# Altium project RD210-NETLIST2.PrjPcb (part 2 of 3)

## Sheet 6.SchDoc
size 609 x 444 mm
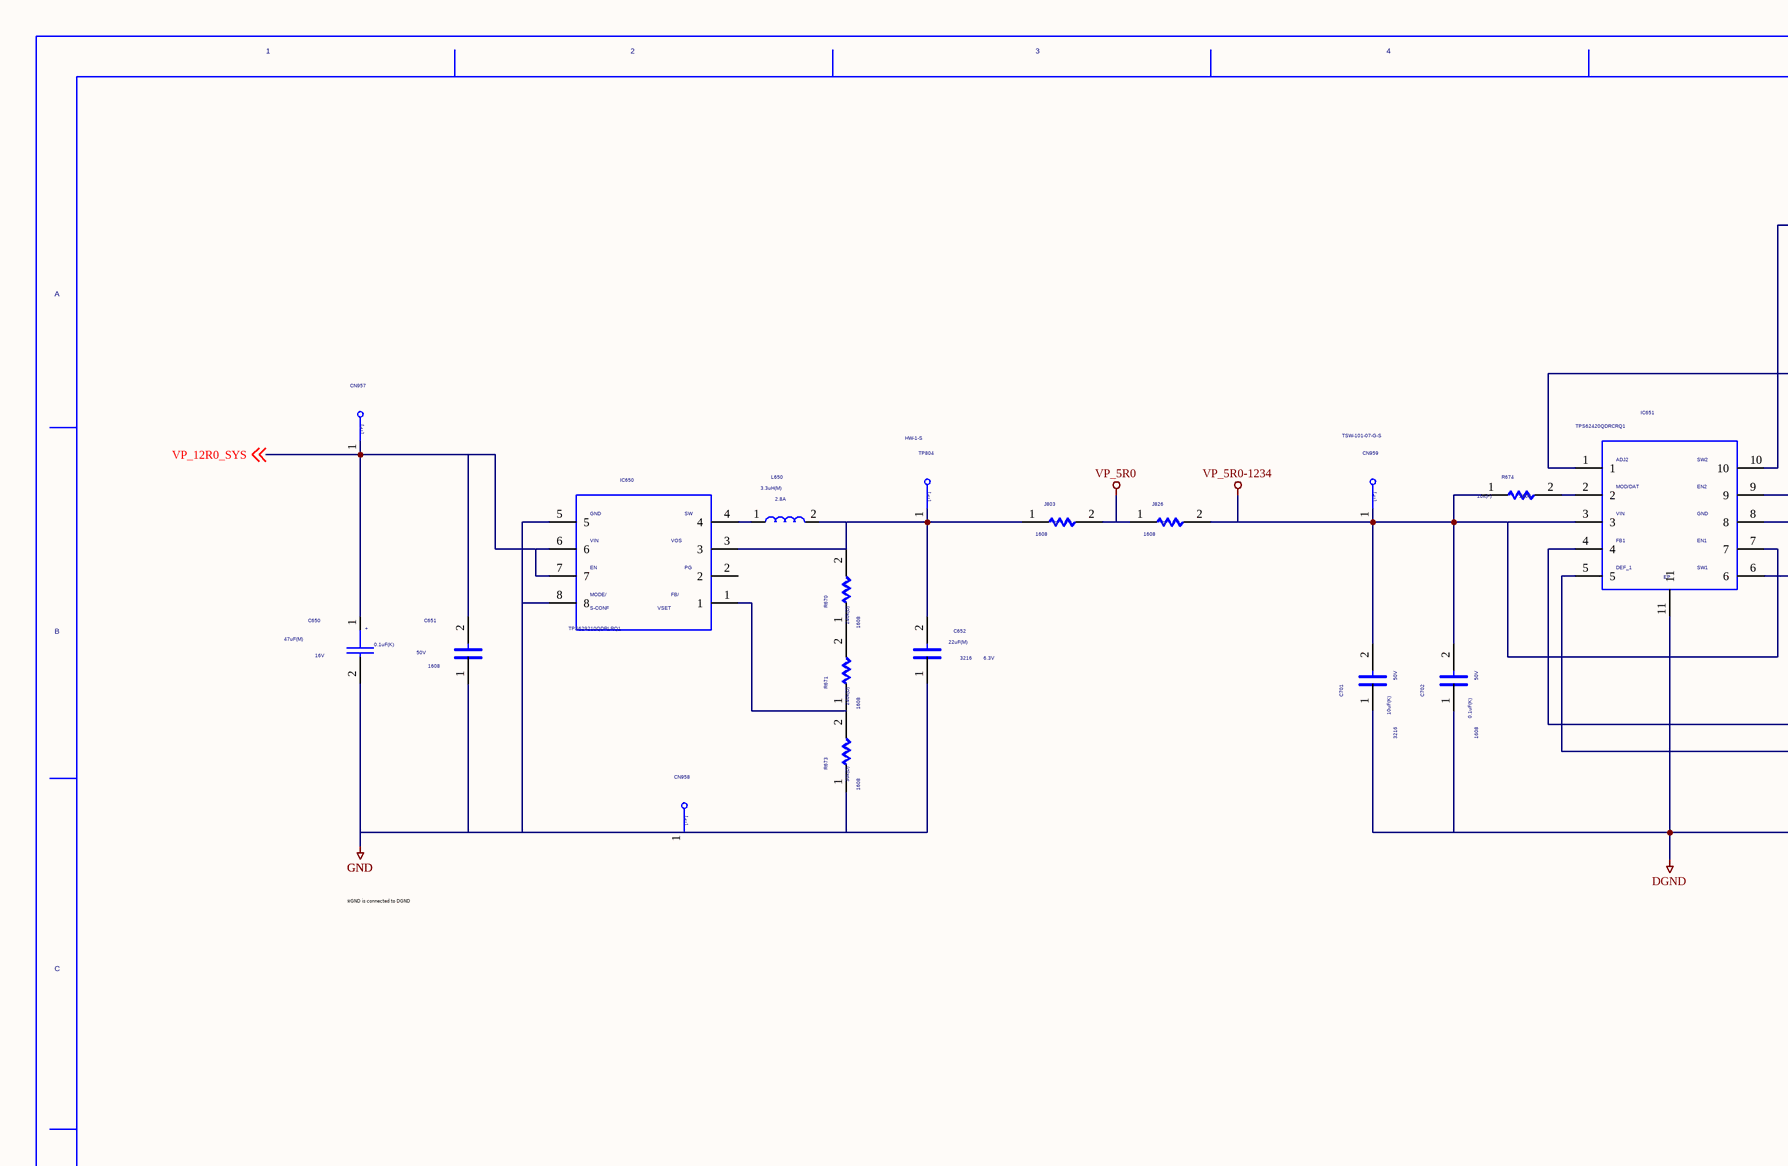
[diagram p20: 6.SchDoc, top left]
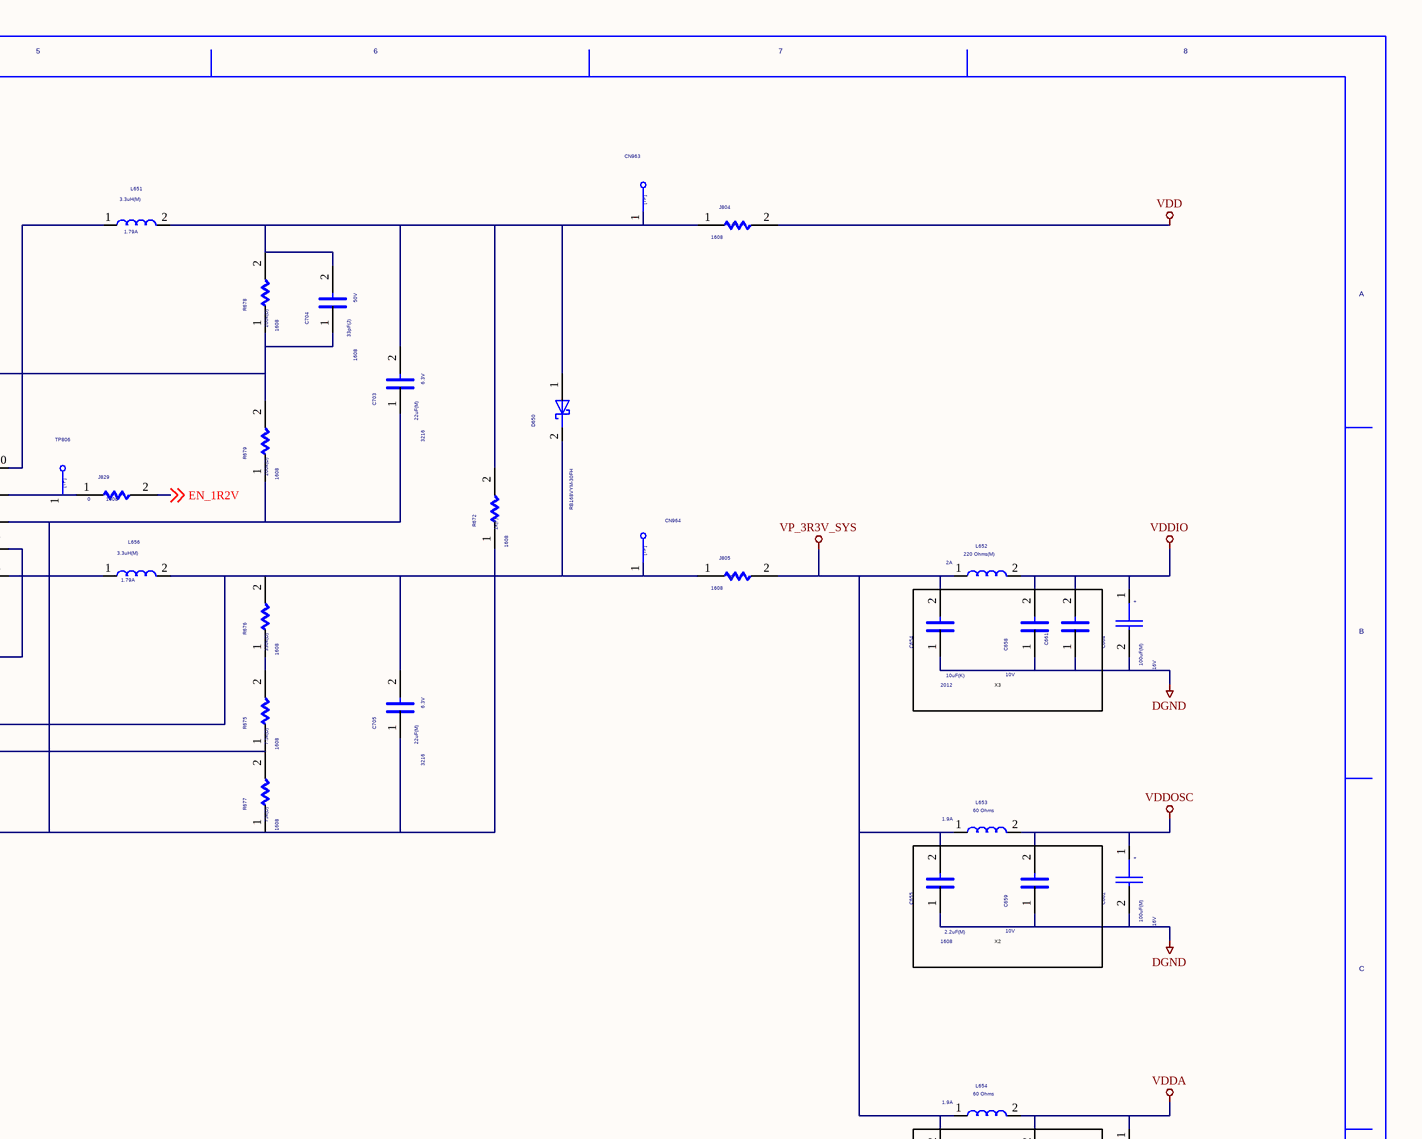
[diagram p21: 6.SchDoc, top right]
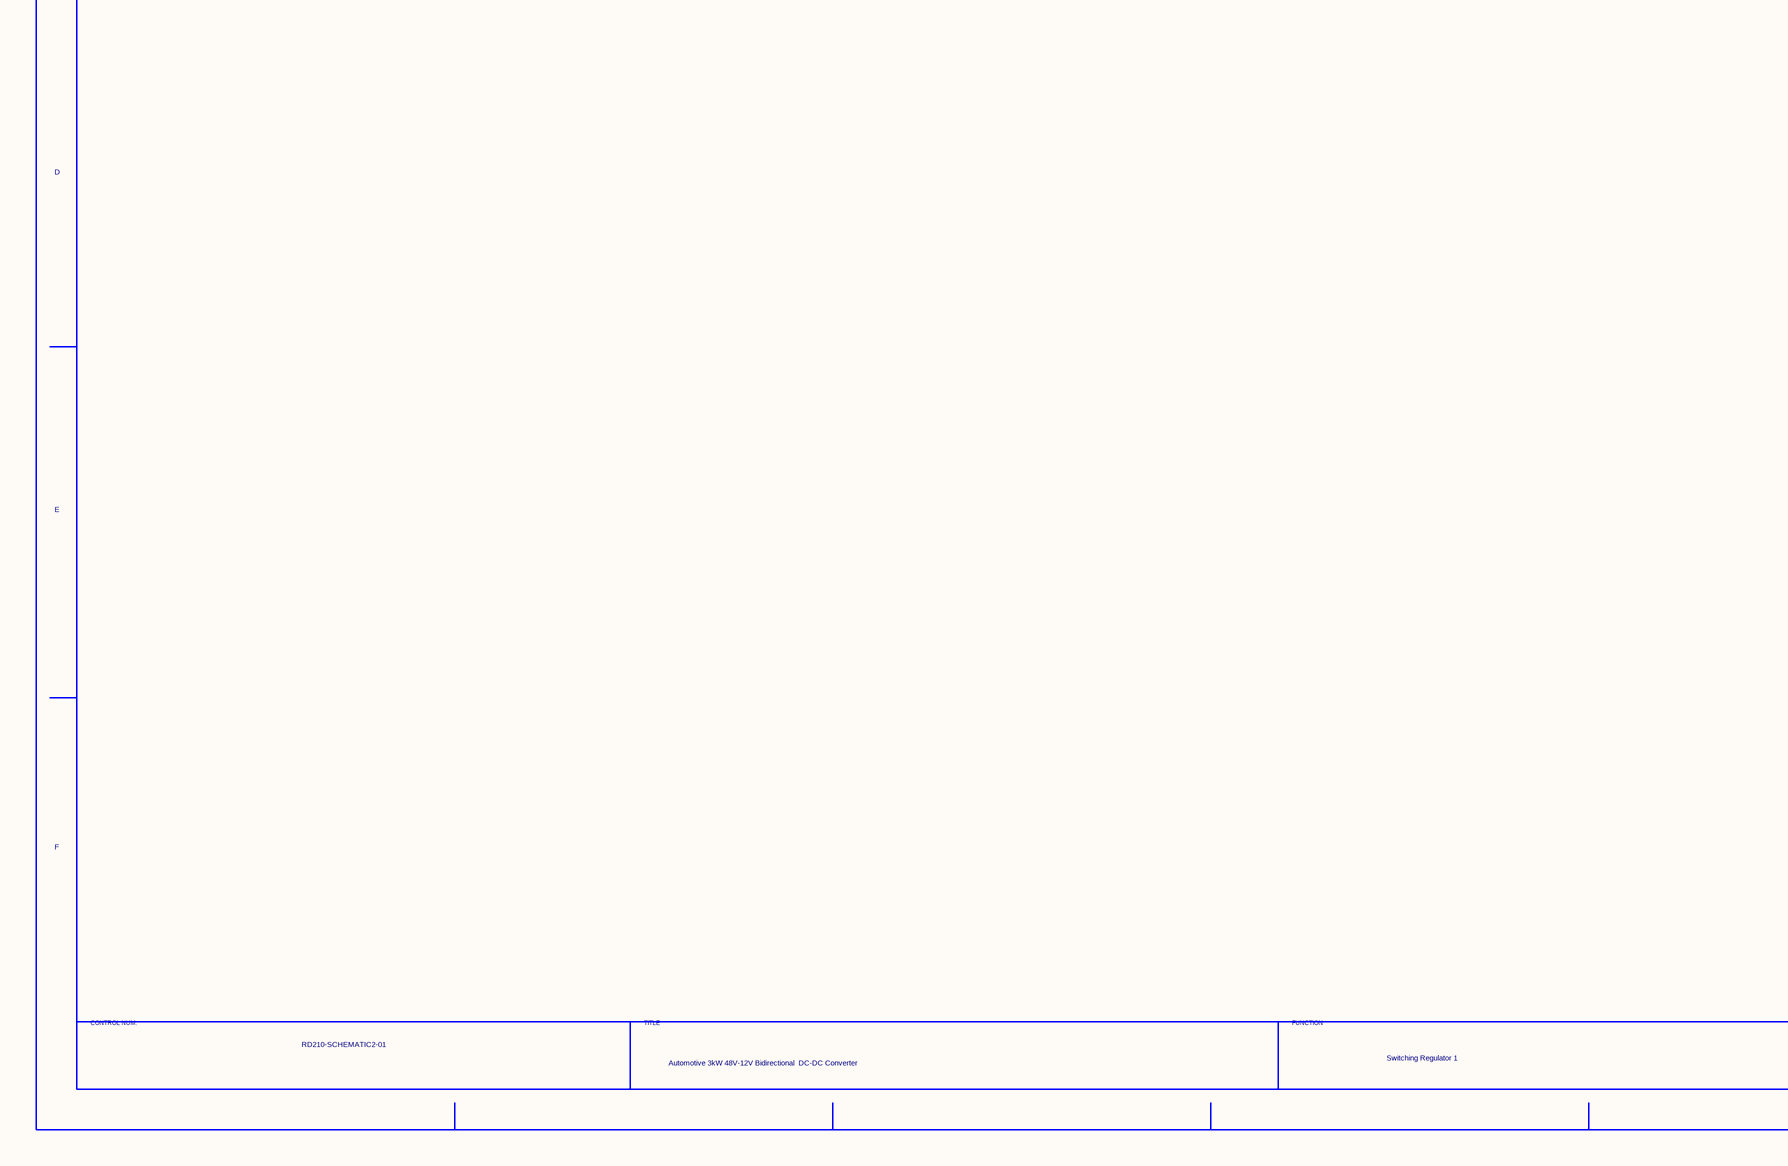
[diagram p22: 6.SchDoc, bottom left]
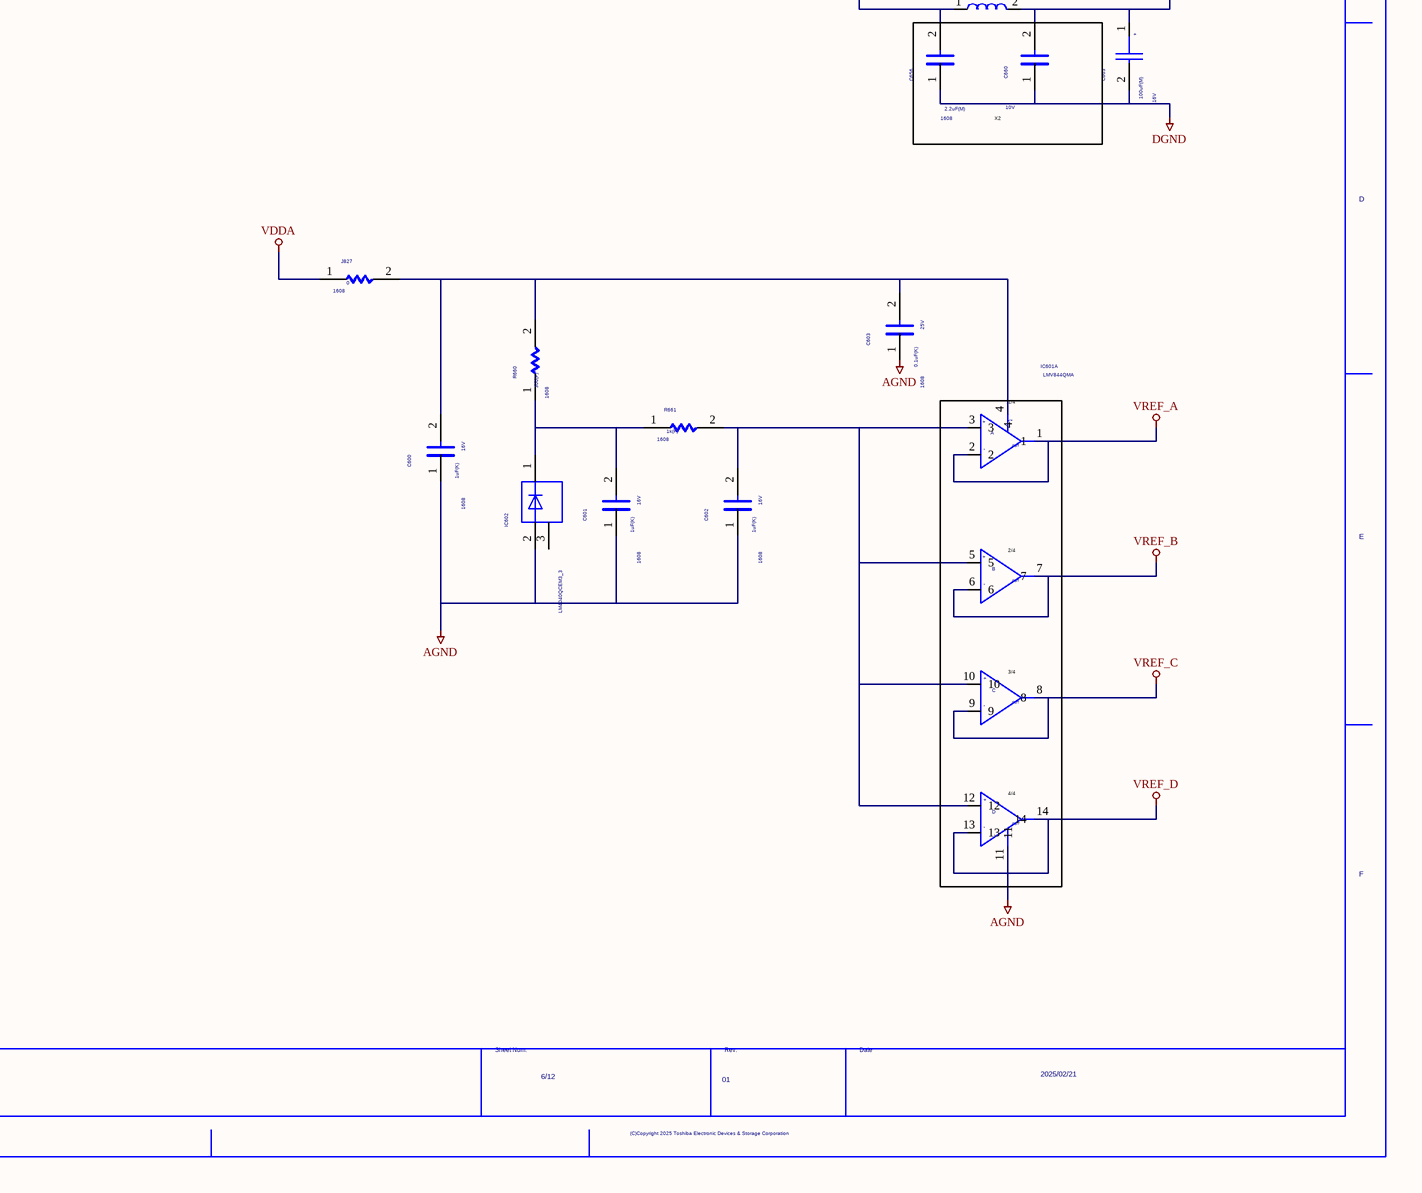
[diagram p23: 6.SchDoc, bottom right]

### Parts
(Parts that share a designator on the sheet are numbered #1, #2 ... from top to bottom, then left to right.)
C600  VAL1: 1uF(K)  VAL2: 16V  SIZECODESMD: 1608  (hidden comment: C)
C601  VAL1: 1uF(K)  VAL2: 16V  SIZECODESMD: 1608  (hidden comment: C)
C602  VAL1: 1uF(K)  VAL2: 16V  SIZECODESMD: 1608  (hidden comment: C)
C603  VAL1: 0.1uF(K)  VAL2: 25V  SIZECODESMD: 1608  (hidden comment: C)
C650  VAL1: 47uF(M)  VAL2: 16V  (hidden comment: CP)
C651  VAL1: 0.1uF(K)  VAL2: 50V  SIZECODESMD: 1608  (hidden comment: C)
C652  VAL1: 22uF(M)  VAL2: 6.3V  SIZECODESMD: 3216  (hidden comment: C)
C654  VAL1: 10uF(K)  VAL2: 10V  SIZECODESMD: 2012  (hidden comment: C)
C655  VAL1: 2.2uF(M)  VAL2: 10V  SIZECODESMD: 1608  (hidden comment: C)
C656  VAL1: 2.2uF(M)  VAL2: 10V  SIZECODESMD: 1608  (hidden comment: C)
C658  C  (value not drawn)
C659  C  (value not drawn)
C660  C  (value not drawn)
C661  C  (value not drawn)
C662  VAL1: 100uF(M)  VAL2: 16V  (hidden comment: CP)
C663  VAL1: 100uF(M)  VAL2: 16V  (hidden comment: CP)
C664  VAL1: 100uF(M)  VAL2: 16V  (hidden comment: CP)
C701  VAL1: 10uF(K)  VAL2: 50V  SIZECODESMD: 3216  (hidden comment: C)
C702  VAL1: 0.1uF(K)  VAL2: 50V  SIZECODESMD: 1608  (hidden comment: C)
C703  VAL1: 22uF(M)  VAL2: 6.3V  SIZECODESMD: 3216  (hidden comment: C)
C704  VAL1: 33pF(J)  VAL2: 50V  SIZECODESMD: 1608  (hidden comment: C)
C705  VAL1: 22uF(M)  VAL2: 6.3V  SIZECODESMD: 3216  (hidden comment: C)
CN957  TP  (value not drawn)
CN958  TP  (value not drawn)
CN959  VAL3: TSW-101-07-G-S  (hidden comment: TP)
CN963  TP  (value not drawn)
CN964  TP  (value not drawn)
D650  VAL3: RB168VYM-30FH  (hidden comment: SBD)
IC601  VAL3: LMV844QMA  (hidden comment: LMV844QMA_1)  (parts A,B,C,D of 4)
IC602  LM4040QCEM3_3
IC650  TPS629210QDRLRQ1
IC651  TPS62420QDRCRQ1
J803  VAL1: 0  SIZECODESMD: 1608  (hidden comment: R)
J804  VAL1: 0  SIZECODESMD: 1608  (hidden comment: R)
J805  VAL1: 0  SIZECODESMD: 1608  (hidden comment: R)
J826  VAL1: 0  SIZECODESMD: 1608  (hidden comment: R)
J827  VAL1: 0  SIZECODESMD: 1608  (hidden comment: R)
J829  VAL1: 0  SIZECODESMD: 1608  (hidden comment: R)
L650  VAL1: 3.3uH(M)  VAL2: 2.8A  (hidden comment: L)
L651  VAL1: 3.3uH(M)  VAL2: 1.79A  (hidden comment: L)
L652  VAL1: 220 Ohms(M)  VAL2: 2A  (hidden comment: L)
L653  VAL1: 60 Ohms  VAL2: 1.9A  (hidden comment: L)
L654  VAL1: 60 Ohms  VAL2: 1.9A  (hidden comment: L)
L656  VAL1: 3.3uH(M)  VAL2: 1.79A  (hidden comment: L)
R660  VAL1: 300(F)  SIZECODESMD: 1608  (hidden comment: R)
R661  VAL1: 1k(F)  SIZECODESMD: 1608  (hidden comment: R)
R670  VAL1: 240k(D)  SIZECODESMD: 1608  (hidden comment: R)
R671  VAL1: 240k(D)  SIZECODESMD: 1608  (hidden comment: R)
R672  VAL1: 1k(F)  SIZECODESMD: 1608  (hidden comment: R)
R673  VAL1: 36k(D)  SIZECODESMD: 1608  (hidden comment: R)
R674  VAL1: 10k(F)  SIZECODESMD: 1608  (hidden comment: R)
R675  VAL1: 7.5k(D)  SIZECODESMD: 1608  (hidden comment: R)
R676  VAL1: 330k(D)  SIZECODESMD: 1608  (hidden comment: R)
R677  VAL1: 75k(D)  SIZECODESMD: 1608  (hidden comment: R)
R678  VAL1: 200k(D)  SIZECODESMD: 1608  (hidden comment: R)
R679  VAL1: 200k(D)  SIZECODESMD: 1608  (hidden comment: R)
TP804  VAL3: HW-1-S  (hidden comment: TP)
TP806  TP  (value not drawn)
U?#6  DATE: 2025/02/21  DRAWINGNUMBER: RD210-SCHEMATIC2-01  TITLE: Automotive 3kW 48V-12V Bidirectional / DC-DC Converter  FUNCTION: Switching Regulator 1  SHEETNUMBER: 6/12  REVISION: 01  (hidden comment: WAKU_DEF_A3)

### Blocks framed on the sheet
X3: C654 C658 C661
X2: C655 C659
X2: C656 C660

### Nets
AGND: C600.1 C601.1 C602.1 C603.1 IC601.11 IC602.2
DGND: C654.1 C655.1 C656.1 C658.1 C659.1 C660.1 C661.1 C662.2 C663.2 C664.2 C701.1 C702.1 C703.1 C705.1 IC651.8 IC651.11 R672.1 R677.1 R679.1
GND: C650.2 C651.1 C652.1 CN958.1 IC650.5 IC650.8 R673.1
VDD: J804.2
VDDA: C660.2 C663.1 J827.1 L654.2
VDDIO: C658.2 C661.2 C664.1 L652.2
VDDOSC: C659.2 C662.1 L653.2
VP_3R3V_SYS: C654.2 C655.2 C656.2 J805.2 L652.1 L653.1 L654.1
VP_5R0: J803.2 J826.1
VP_5R0-1234: C701.2 C702.2 CN959.1 IC651.3 IC651.7 J826.2 R674.1
VREF_A: IC601.1 IC601.2
VREF_B: IC601.6 IC601.7
VREF_C: IC601.8 IC601.9
VREF_D: IC601.13 IC601.14
EN_1R2V: J829.2 ; off-sheet EN_1R2V
SIG889: IC650.4 L650.1
SIG891: IC650.1 R671.1 R673.2
SIG893: C652.2 IC650.3 J803.1 L650.2 R670.2 TP804.1
SIG894: IC651.2 R674.2
SIG895: IC651.6 L656.1
SIG896: IC651.10 L651.1
SIG898: C704.1 IC651.1 R678.1 R679.2
SIG901: R675.2 R676.1
SIG902: IC651.5 R675.1 R677.2
SIG903: IC651.9 J829.1 TP806.1
SIG905: C703.2 C704.2 CN963.1 D650.1(A) J804.1 L651.2 R672.2 R678.2
SIG909: C705.2 CN964.1 D650.2(C) IC651.4 J805.1 L656.2 R676.2
SIG914: C600.2 C603.2 IC601.4 J827.2 R660.2
SIG916: C601.2 IC602.1 R660.1 R661.1
SIG918: C602.2 IC601.3 IC601.5 IC601.10 IC601.12 R661.2
VP_12R0_SYS: C650.1 C651.2 CN957.1 IC650.6 IC650.7 ; off-sheet VP_12R0_SYS
NetR670_1: R670.1 R671.2

Not connected (* = marked no-connect by the designer): IC602 3; IC650 2

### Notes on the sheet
- ※GND is connected to DGND
- (near IC601) 1/4
- (near IC601) 2/4
- (near IC601) 3/4
- (near IC601) 4/4

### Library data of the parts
C600-C603 C651 C652 C654-C656 C701-C705 = C: OriginalSymbolOrigin: (2540,7620)
C650 = CP: SQ_PART_MODEL: CON_47U; SAVEAREA0: -1450,-153,20294,13055; SAVECOUNT: 52; TIME: 15:02:55; UPDATEUSER: fukuda-y; UPDATETIME: 16:13:42; OriginalSymbolOrigin: (2540,10160); CDBNAME: C; MAXGCOUNT: 1; ADSCNVFLAG: ON
C658 C661 = C: VAL1: 10uF(K); VAL2: 10V; OriginalSymbolOrigin: (2540,7620); SIZECODESMD: 2012
C659 C660 = C: VAL1: 2.2uF(M); VAL2: 10V; OriginalSymbolOrigin: (2540,7620); SIZECODESMD: 1608
C662-C664 = CP: SAVEAREA0: -1450,-153,20294,13055; SAVECOUNT: 52; TIME: 15:02:55; UPDATEUSER: fukuda-y; UPDATETIME: 16:13:42; OriginalSymbolOrigin: (2540,10160); CDBNAME: C
CN957 CN958 CN963 CN964 = TP: TIME: 16:12:21; UPDATEUSER: fukuda-y; UPDATETIME: 16:18:11; SAVECOUNT: 2; SAVEAREA0: -242,-92,12810,7836; OriginalSymbolOrigin: (0,7620); VAL3: TSW-101-07-G-S; CDBNAME: CN
CN959 = TP: TIME: 16:12:21; UPDATEUSER: fukuda-y; UPDATETIME: 16:18:11; SAVECOUNT: 2; SAVEAREA0: -242,-92,12810,7836; OriginalSymbolOrigin: (0,7620); CDBNAME: CN
D650 = SBD: SAVEAREA0: -4630,-153,17114,13055; TIME: 14:49:55; UPDATEUSER: fukuda-y; UPDATETIME: 08:16:22; SAVECOUNT: 9; OriginalSymbolOrigin: (5080,5080); CDBNAME: D
IC601 = LMV844QMA_1: MANUFACTURER: TOSHIBA; ITEM: IC Logic; TIME: 08:44:45; UPDATEUSER: sptcae13; UPDATETIME: 10:49:44; SAVECOUNT: 16; SAVEAREA0: -10101,-18267,23348,18085; OriginalSymbolOrigin: (2540,0); CaptureCellPackProp: LMV844QMA_1A
IC602 = LM4040QCEM3_3: 7TH PART FIELD: RES.,; 4TH PART FIELD: VISHAY,; 3RD PART FIELD: CHIP; 2ND PART FIELD: 1-5%; 5TH PART FIELD: CRCW0805---RT6; 1ST PART FIELD: 1/8W; TIME: 08:44:45; UPDATEUSER: sptcae13; UPDATETIME: 10:00:08; SAVECOUNT: 4; SAVEAREA0: -29906,-23716,24621,6120; OriginalSymbolOrigin: (2540,-5080); CDBNAME: IC
IC650 = TPS629210QDRLRQ1: MANUFACTURER: Panasonic; ITEM: Register; VAL2: 1/10W; SIZECODESMD: 1608; VALUE4: (B); COMP: IC; VAL1: 4.99k; TIME: 08:44:47; UPDATEUSER: sptcae13; UPDATETIME: 13:49:45; SAVECOUNT: 4; SAVEAREA0: -66056,-44069,81279,36552; OriginalSymbolOrigin: (5080,0)
IC651 = TPS62420QDRCRQ1: MANUFACTURER: Panasonic; ITEM: Register; VAL2: 1/10W; SIZECODESMD: 1608; VALUE4: (B); VAL1: 4.99k; TIME: 08:44:47; UPDATEUSER: sptcae13; UPDATETIME: 20:00:27; SAVECOUNT: 8; SAVEAREA0: -17963,-39434,54634,13711; OriginalSymbolOrigin: (5080,0); CDBNAME: IC
J803-J805 J826 J827 J829 = R: OriginalSymbolOrigin: (5080,5080); CDBNAME: JP
L650 = L: OriginalSymbolOrigin: (2540,5080); VAL3: XGL3520-332MEC
L651 L656 = L: OriginalSymbolOrigin: (2540,5080); VAL3: VLS3015CX-3R3M-H
L652 = L: OriginalSymbolOrigin: (2540,5080); VAL3: BLM21PG221SN1D
L653 L654 = L: OriginalSymbolOrigin: (2540,5080); VAL3: BLM21PG600BH1
R660 R661 R670-R679 = R: VAL2: 200mW; OriginalSymbolOrigin: (5080,5080)
TP804 = TP: TIME: 16:12:21; UPDATEUSER: fukuda-y; UPDATETIME: 16:18:11; SAVECOUNT: 2; SAVEAREA0: -242,-92,12810,7836; OriginalSymbolOrigin: (0,7620)
TP806 = TP: TIME: 16:12:21; UPDATEUSER: fukuda-y; UPDATETIME: 16:18:11; SAVECOUNT: 2; SAVEAREA0: -242,-92,12810,7836; OriginalSymbolOrigin: (0,7620); VAL3: HW-1-S
U?#6 = WAKU_DEF_A3: PLOTTIME: HH:MM; SAVEAREA0: 96913,-567914,509243,-368858; TIME: 13:37:44; UPDATEUSER: t5459927; UPDATETIME: 14:05:32; SAVECOUNT: 8; ZONEOFFSETX: 36; ZONEOFFSETY: -24; OriginalSymbolOrigin: (12700,-12700); SHTSAVECOUNT: 53

## Sheet 7.SchDoc
size 609 x 444 mm
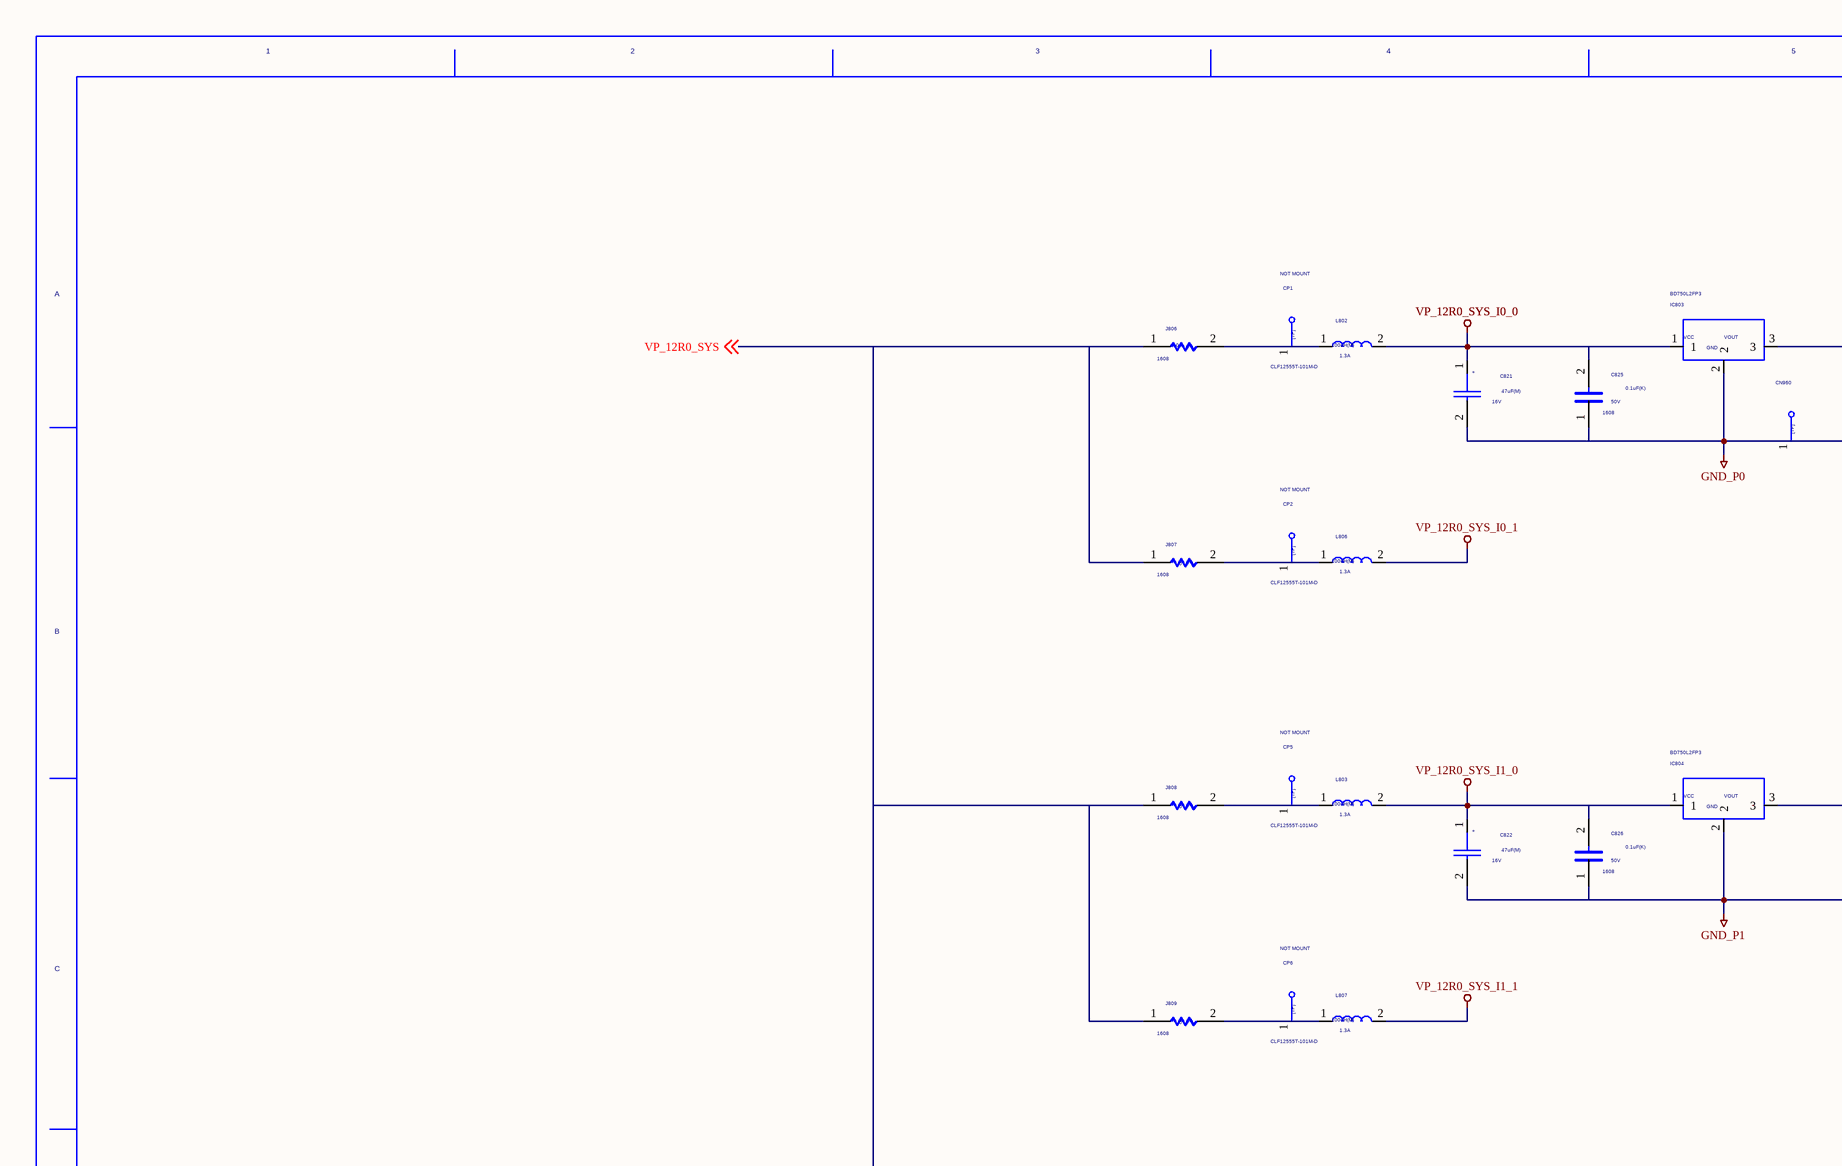
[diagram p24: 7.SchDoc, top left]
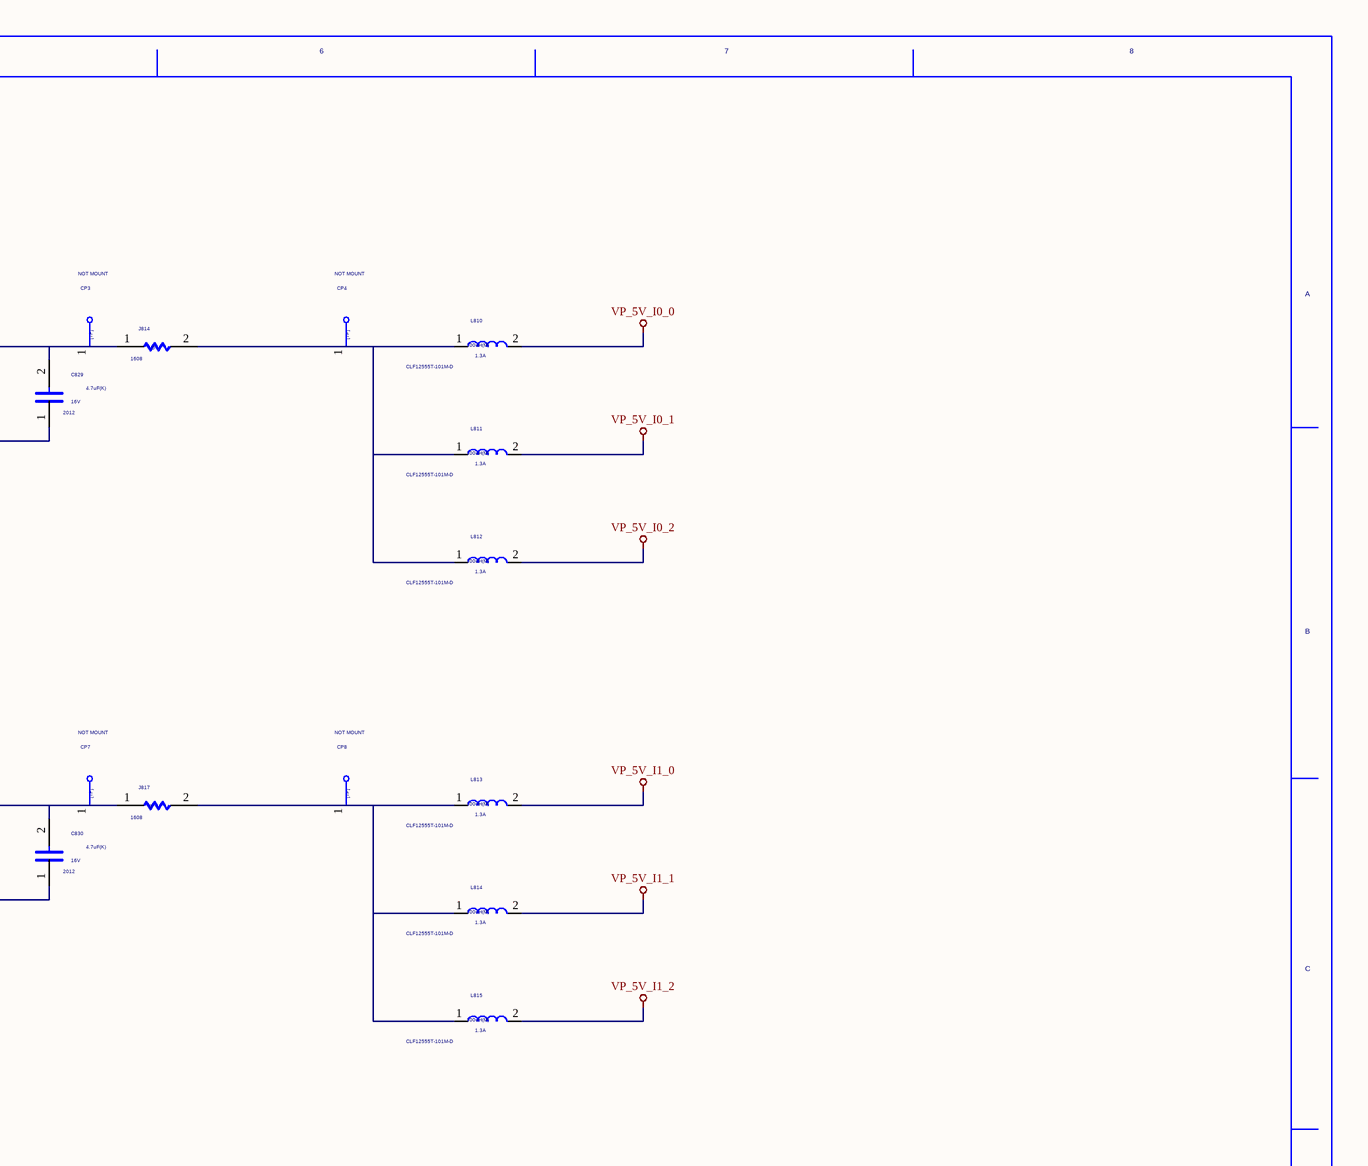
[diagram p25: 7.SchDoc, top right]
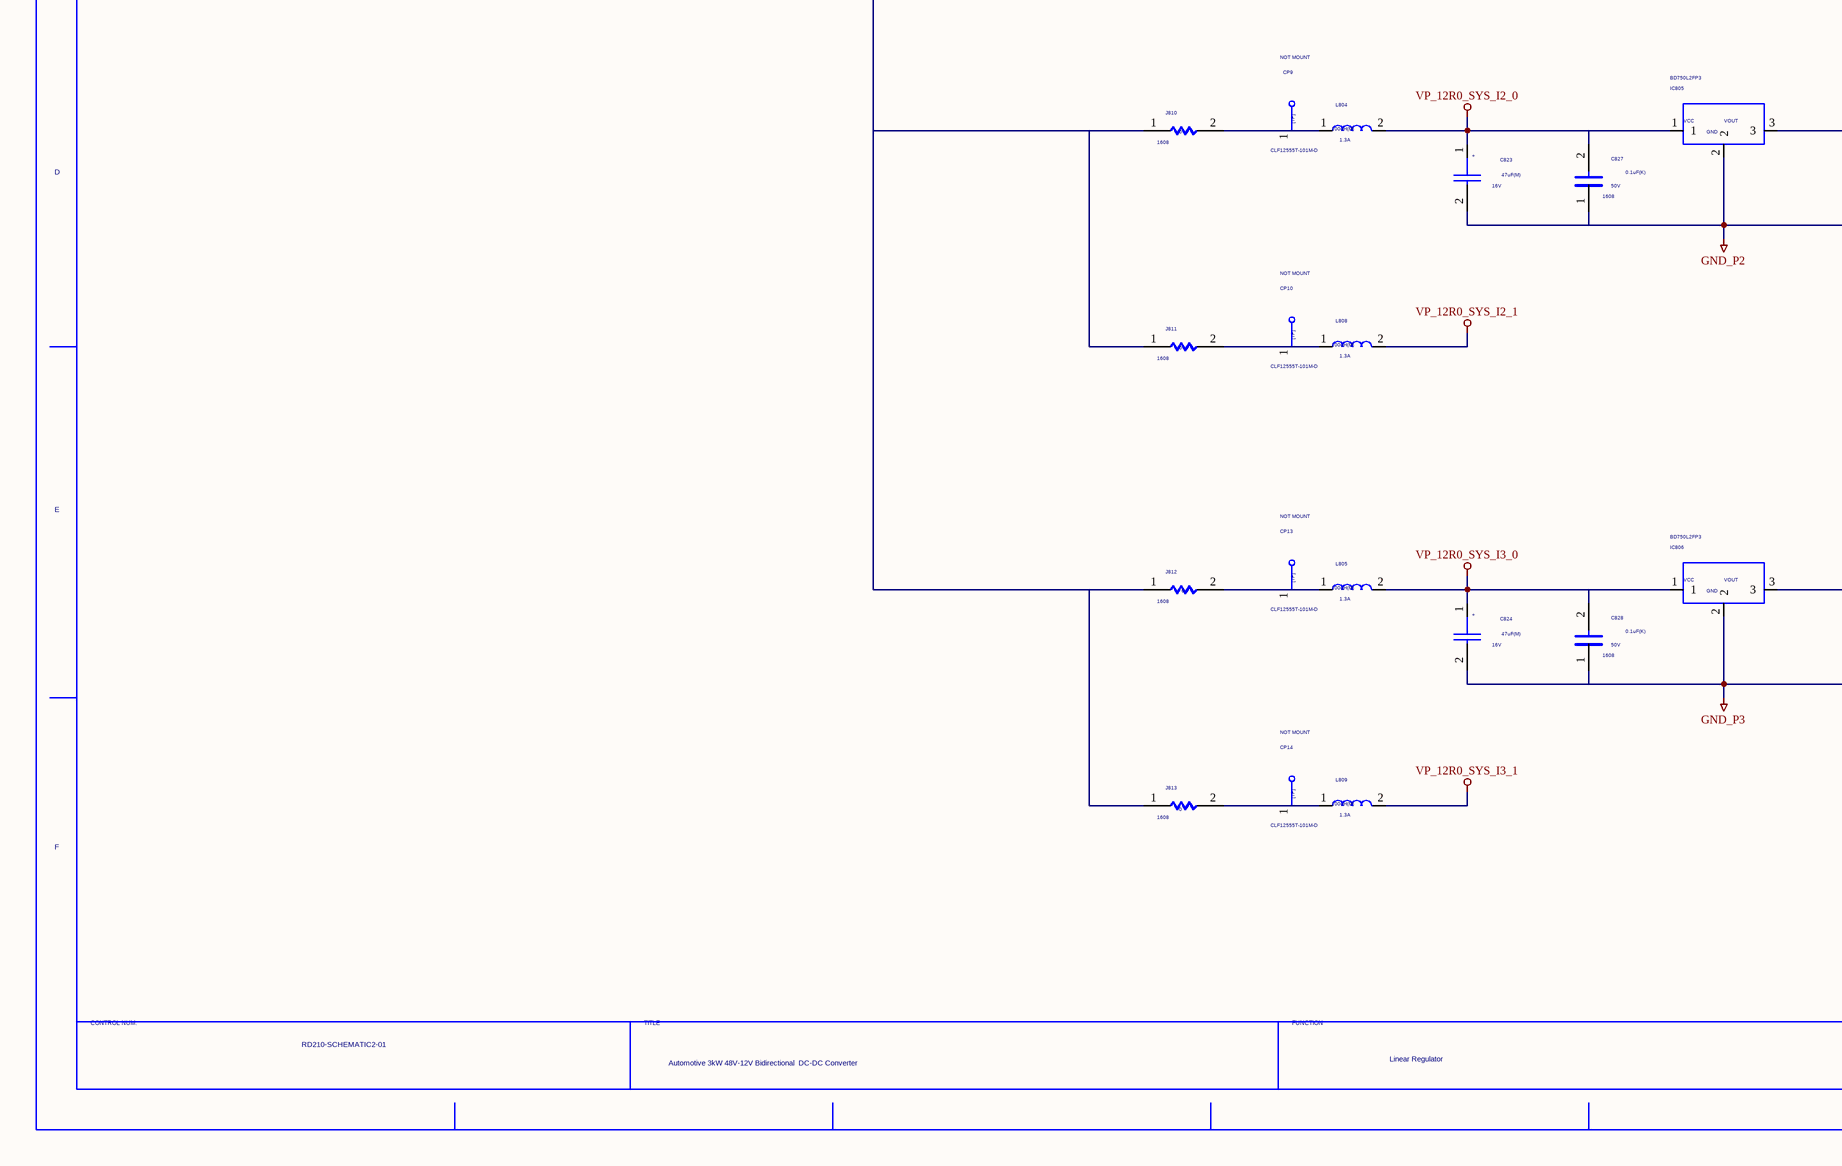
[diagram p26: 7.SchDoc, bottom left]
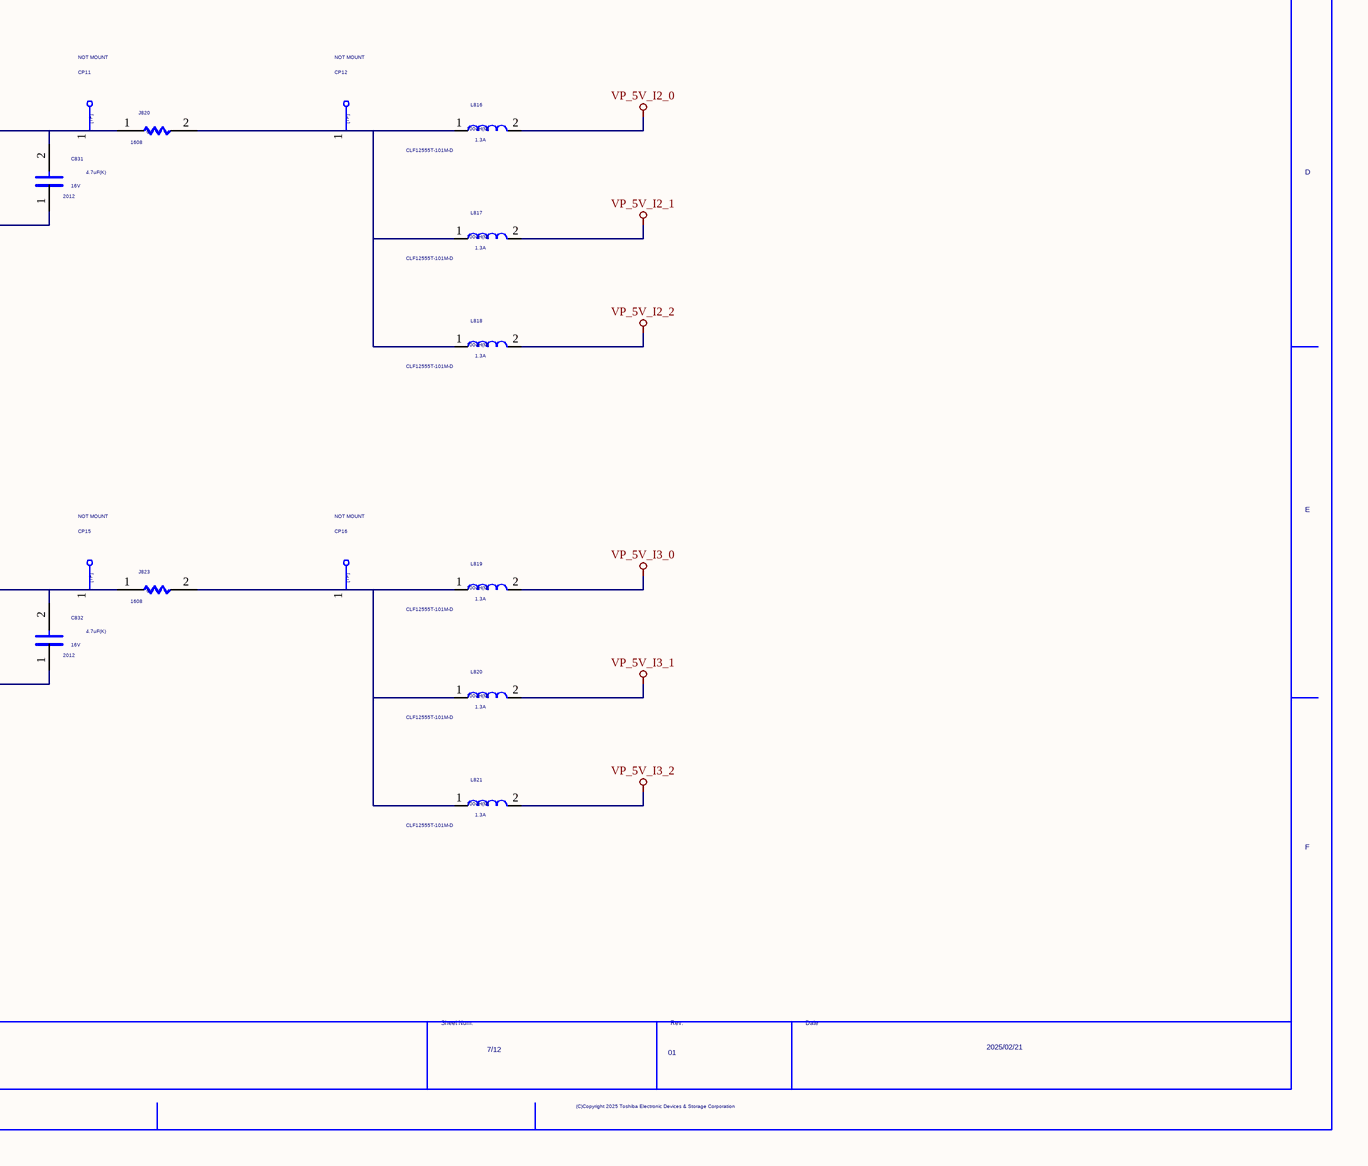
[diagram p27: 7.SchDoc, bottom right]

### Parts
(Parts that share a designator on the sheet are numbered #1, #2 ... from top to bottom, then left to right.)
C821  VAL1: 47uF(M)  VAL2: 16V  (hidden comment: CP)
C822  VAL1: 47uF(M)  VAL2: 16V  (hidden comment: CP)
C823  VAL1: 47uF(M)  VAL2: 16V  (hidden comment: CP)
C824  VAL1: 47uF(M)  VAL2: 16V  (hidden comment: CP)
C825  VAL1: 0.1uF(K)  VAL2: 50V  SIZECODESMD: 1608  (hidden comment: C)
C826  VAL1: 0.1uF(K)  VAL2: 50V  SIZECODESMD: 1608  (hidden comment: C)
C827  VAL1: 0.1uF(K)  VAL2: 50V  SIZECODESMD: 1608  (hidden comment: C)
C828  VAL1: 0.1uF(K)  VAL2: 50V  SIZECODESMD: 1608  (hidden comment: C)
C829  VAL1: 4.7uF(K)  VAL2: 16V  SIZECODESMD: 2012  (hidden comment: C)
C830  VAL1: 4.7uF(K)  VAL2: 16V  SIZECODESMD: 2012  (hidden comment: C)
C831  VAL1: 4.7uF(K)  VAL2: 16V  SIZECODESMD: 2012  (hidden comment: C)
C832  VAL1: 4.7uF(K)  VAL2: 16V  SIZECODESMD: 2012  (hidden comment: C)
CN960  TP  (value not drawn)
CP1  NOTMOUNT: NOT MOUNT  (hidden comment: TP)
CP2  NOTMOUNT: NOT MOUNT  (hidden comment: TP)
CP3  NOTMOUNT: NOT MOUNT  (hidden comment: TP)
CP4  NOTMOUNT: NOT MOUNT  (hidden comment: TP)
CP5  NOTMOUNT: NOT MOUNT  (hidden comment: TP)
CP6  NOTMOUNT: NOT MOUNT  (hidden comment: TP)
CP7  NOTMOUNT: NOT MOUNT  (hidden comment: TP)
CP8  NOTMOUNT: NOT MOUNT  (hidden comment: TP)
CP9  NOTMOUNT: NOT MOUNT  (hidden comment: TP)
CP10  NOTMOUNT: NOT MOUNT  (hidden comment: TP)
CP11  NOTMOUNT: NOT MOUNT  (hidden comment: TP)
CP12  NOTMOUNT: NOT MOUNT  (hidden comment: TP)
CP13  NOTMOUNT: NOT MOUNT  (hidden comment: TP)
CP14  NOTMOUNT: NOT MOUNT  (hidden comment: TP)
CP15  NOTMOUNT: NOT MOUNT  (hidden comment: TP)
CP16  NOTMOUNT: NOT MOUNT  (hidden comment: TP)
IC803  BD750L2FP3
IC804  BD750L2FP3
IC805  BD750L2FP3
IC806  BD750L2FP3
J806  VAL1: 0  SIZECODESMD: 1608  (hidden comment: R)
J807  VAL1: 0  SIZECODESMD: 1608  (hidden comment: R)
J808  VAL1: 0  SIZECODESMD: 1608  (hidden comment: R)
J809  VAL1: 0  SIZECODESMD: 1608  (hidden comment: R)
J810  VAL1: 0  SIZECODESMD: 1608  (hidden comment: R)
J811  VAL1: 0  SIZECODESMD: 1608  (hidden comment: R)
J812  VAL1: 0  SIZECODESMD: 1608  (hidden comment: R)
J813  VAL1: 0  SIZECODESMD: 1608  (hidden comment: R)
J814  VAL1: 0  SIZECODESMD: 1608  (hidden comment: R)
J817  VAL1: 0  SIZECODESMD: 1608  (hidden comment: R)
J820  VAL1: 0  SIZECODESMD: 1608  (hidden comment: R)
J823  VAL1: 0  SIZECODESMD: 1608  (hidden comment: R)
L802  VAL1: 100uH(M)  VAL2: 1.3A  VAL3: CLF12555T-101M-D  (hidden comment: L)
L803  VAL1: 100uH(M)  VAL2: 1.3A  VAL3: CLF12555T-101M-D  (hidden comment: L)
L804  VAL1: 100uH(M)  VAL2: 1.3A  VAL3: CLF12555T-101M-D  (hidden comment: L)
L805  VAL1: 100uH(M)  VAL2: 1.3A  VAL3: CLF12555T-101M-D  (hidden comment: L)
L806  VAL1: 100uH(M)  VAL2: 1.3A  VAL3: CLF12555T-101M-D  (hidden comment: L)
L807  VAL1: 100uH(M)  VAL2: 1.3A  VAL3: CLF12555T-101M-D  (hidden comment: L)
L808  VAL1: 100uH(M)  VAL2: 1.3A  VAL3: CLF12555T-101M-D  (hidden comment: L)
L809  VAL1: 100uH(M)  VAL2: 1.3A  VAL3: CLF12555T-101M-D  (hidden comment: L)
L810  VAL1: 100uH(M)  VAL2: 1.3A  VAL3: CLF12555T-101M-D  (hidden comment: L)
L811  VAL1: 100uH(M)  VAL2: 1.3A  VAL3: CLF12555T-101M-D  (hidden comment: L)
L812  VAL1: 100uH(M)  VAL2: 1.3A  VAL3: CLF12555T-101M-D  (hidden comment: L)
L813  VAL1: 100uH(M)  VAL2: 1.3A  VAL3: CLF12555T-101M-D  (hidden comment: L)
L814  VAL1: 100uH(M)  VAL2: 1.3A  VAL3: CLF12555T-101M-D  (hidden comment: L)
L815  VAL1: 100uH(M)  VAL2: 1.3A  VAL3: CLF12555T-101M-D  (hidden comment: L)
L816  VAL1: 100uH(M)  VAL2: 1.3A  VAL3: CLF12555T-101M-D  (hidden comment: L)
L817  VAL1: 100uH(M)  VAL2: 1.3A  VAL3: CLF12555T-101M-D  (hidden comment: L)
L818  VAL1: 100uH(M)  VAL2: 1.3A  VAL3: CLF12555T-101M-D  (hidden comment: L)
L819  VAL1: 100uH(M)  VAL2: 1.3A  VAL3: CLF12555T-101M-D  (hidden comment: L)
L820  VAL1: 100uH(M)  VAL2: 1.3A  VAL3: CLF12555T-101M-D  (hidden comment: L)
L821  VAL1: 100uH(M)  VAL2: 1.3A  VAL3: CLF12555T-101M-D  (hidden comment: L)
U?#7  DATE: 2025/02/21  DRAWINGNUMBER: RD210-SCHEMATIC2-01  TITLE: Automotive 3kW 48V-12V Bidirectional / DC-DC Converter  FUNCTION: Linear Regulator  SHEETNUMBER: 7/12  REVISION: 01  (hidden comment: WAKU_DEF_A3)

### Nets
GND_P0: C821.2 C825.1 C829.1 CN960.1 IC803.2
GND_P1: C822.2 C826.1 C830.1 IC804.2
GND_P2: C823.2 C827.1 C831.1 IC805.2
GND_P3: C824.2 C828.1 C832.1 IC806.2
VP_5V_I0_0: L810.2
VP_5V_I0_1: L811.2
VP_5V_I0_2: L812.2
VP_5V_I1_0: L813.2
VP_5V_I1_1: L814.2
VP_5V_I1_2: L815.2
VP_5V_I2_0: L816.2
VP_5V_I2_1: L817.2
VP_5V_I2_2: L818.2
VP_5V_I3_0: L819.2
VP_5V_I3_1: L820.2
VP_5V_I3_2: L821.2
VP_12R0_SYS_I0_0: C821.1 C825.2 IC803.1 L802.2
VP_12R0_SYS_I0_1: L806.2
VP_12R0_SYS_I1_0: C822.1 C826.2 IC804.1 L803.2
VP_12R0_SYS_I1_1: L807.2
VP_12R0_SYS_I2_0: C823.1 C827.2 IC805.1 L804.2
VP_12R0_SYS_I2_1: L808.2
VP_12R0_SYS_I3_0: C824.1 C828.2 IC806.1 L805.2
VP_12R0_SYS_I3_1: L809.2
SIG924: CP1.1 J806.2 L802.1
SIG926: C829.2 CP3.1 IC803.3 J814.1
SIG927: CP4.1 J814.2 L810.1 L811.1 L812.1
SIG929: CP2.1 J807.2 L806.1
SIG930: CP6.1 J809.2 L807.1
SIG931: C830.2 CP7.1 IC804.3 J817.1
SIG932: CP8.1 J817.2 L813.1 L814.1 L815.1
SIG933: CP5.1 J808.2 L803.1
SIG934: CP10.1 J811.2 L808.1
SIG935: C832.2 CP15.1 IC806.3 J823.1
SIG936: C831.2 CP11.1 IC805.3 J820.1
SIG937: CP12.1 J820.2 L816.1 L817.1 L818.1
SIG938: CP14.1 J813.2 L809.1
SIG939: CP9.1 J810.2 L804.1
SIG940: CP13.1 J812.2 L805.1
SIG941: CP16.1 J823.2 L819.1 L820.1 L821.1
VP_12R0_SYS: J806.1 J807.1 J808.1 J809.1 J810.1 J811.1 J812.1 J813.1 ; off-sheet VP_12R0_SYS

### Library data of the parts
C821-C824 = CP: as C662 on sheet 6
C825-C832 = C: OriginalSymbolOrigin: (2540,7620)
CN960 = TP: TIME: 16:12:21; UPDATEUSER: fukuda-y; UPDATETIME: 16:18:11; SAVECOUNT: 2; SAVEAREA0: -242,-92,12810,7836; OriginalSymbolOrigin: (0,7620); VAL3: HW-1-S; CDBNAME: CN
CP1-CP16 = TP: TIME: 16:12:21; UPDATEUSER: fukuda-y; UPDATETIME: 16:18:11; SAVECOUNT: 2; SAVEAREA0: -242,-92,12810,7836; OriginalSymbolOrigin: (0,7620); CDBNAME: CP
IC803-IC806 = BD750L2FP3: MANUFACTURER: PANASONIC; ITEM: CAP Film; TIME: 08:44:47; UPDATEUSER: sptcae13; UPDATETIME: 11:25:10; SAVECOUNT: 4; SAVEAREA0: -24389,-27959,34535,4284; OriginalSymbolOrigin: (2540,0); CDBNAME: IC
J806-J814 J817 J820 J823 = R: as J803 on sheet 6
L802-L821 = L: OriginalSymbolOrigin: (2540,5080)
U?#7 = WAKU_DEF_A3: PLOTTIME: HH:MM; SAVEAREA0: 96913,-567914,509243,-368858; TIME: 11:07:30; UPDATEUSER: t5459927; UPDATETIME: 06:47:03; SAVECOUNT: 8; ZONEOFFSETX: 36; ZONEOFFSETY: -24; OriginalSymbolOrigin: (12700,-12700); SHTSAVECOUNT: 20

## Sheet 8.SchDoc
size 609 x 444 mm
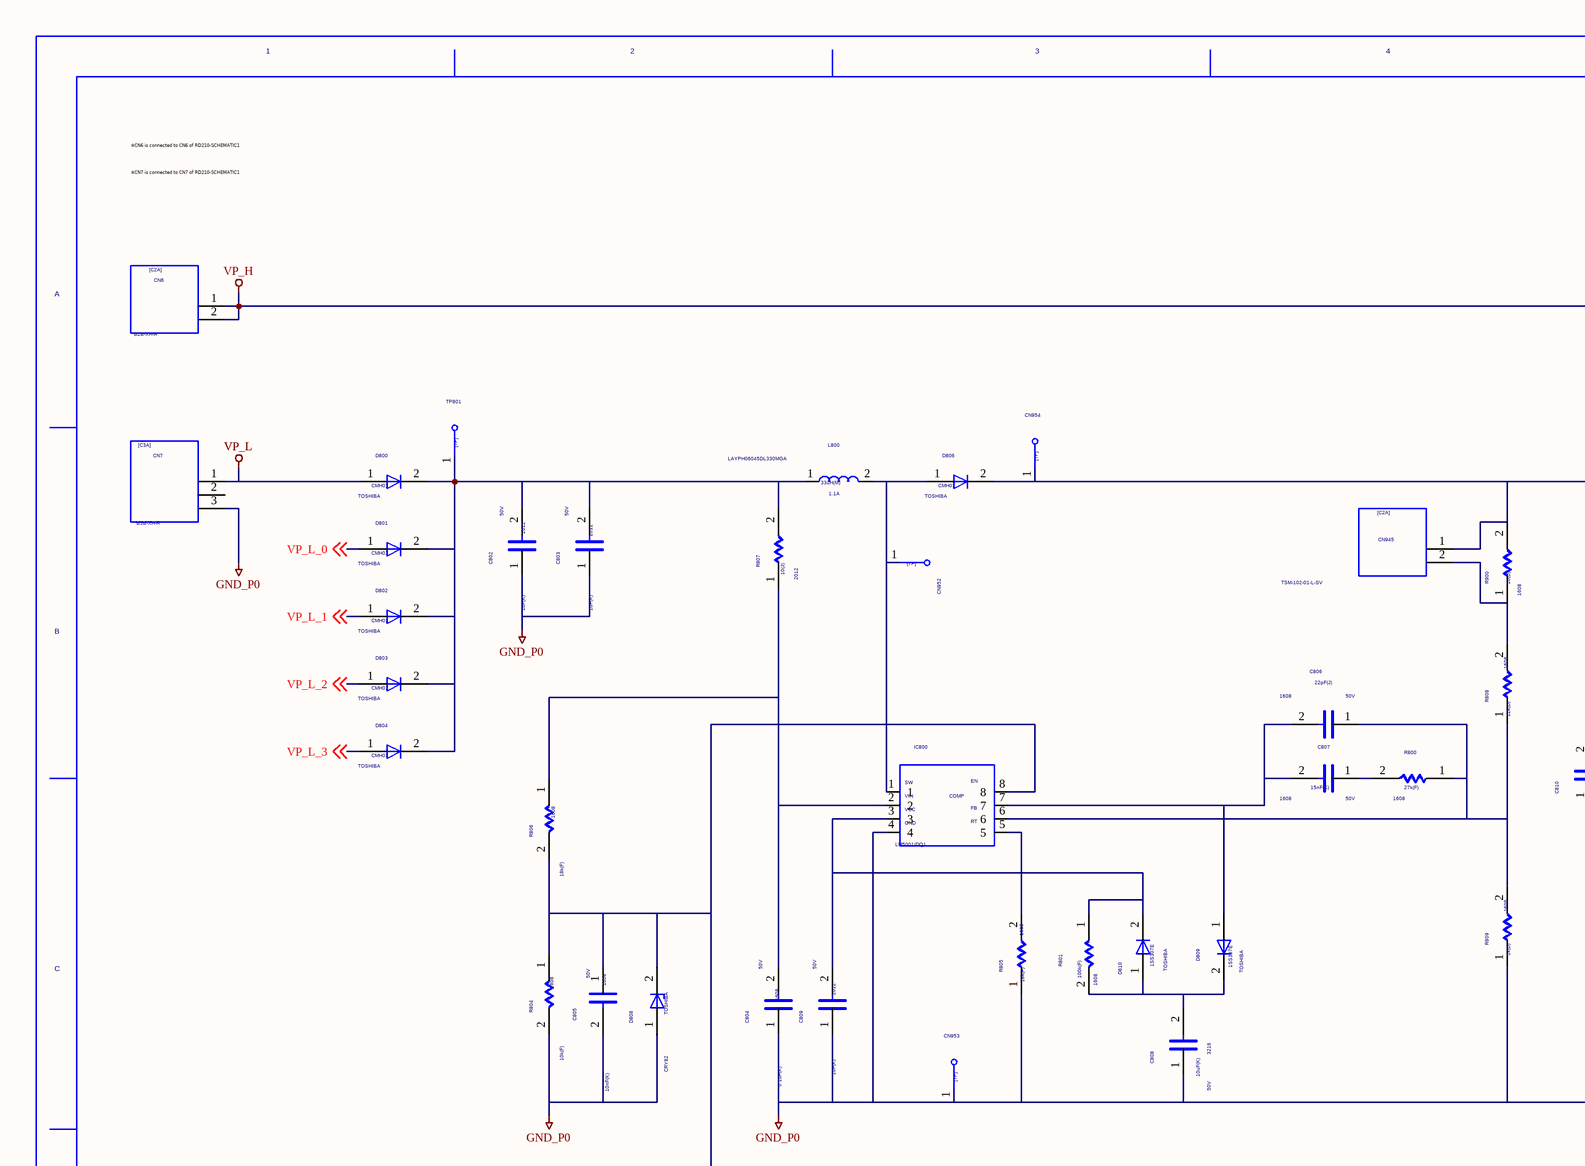
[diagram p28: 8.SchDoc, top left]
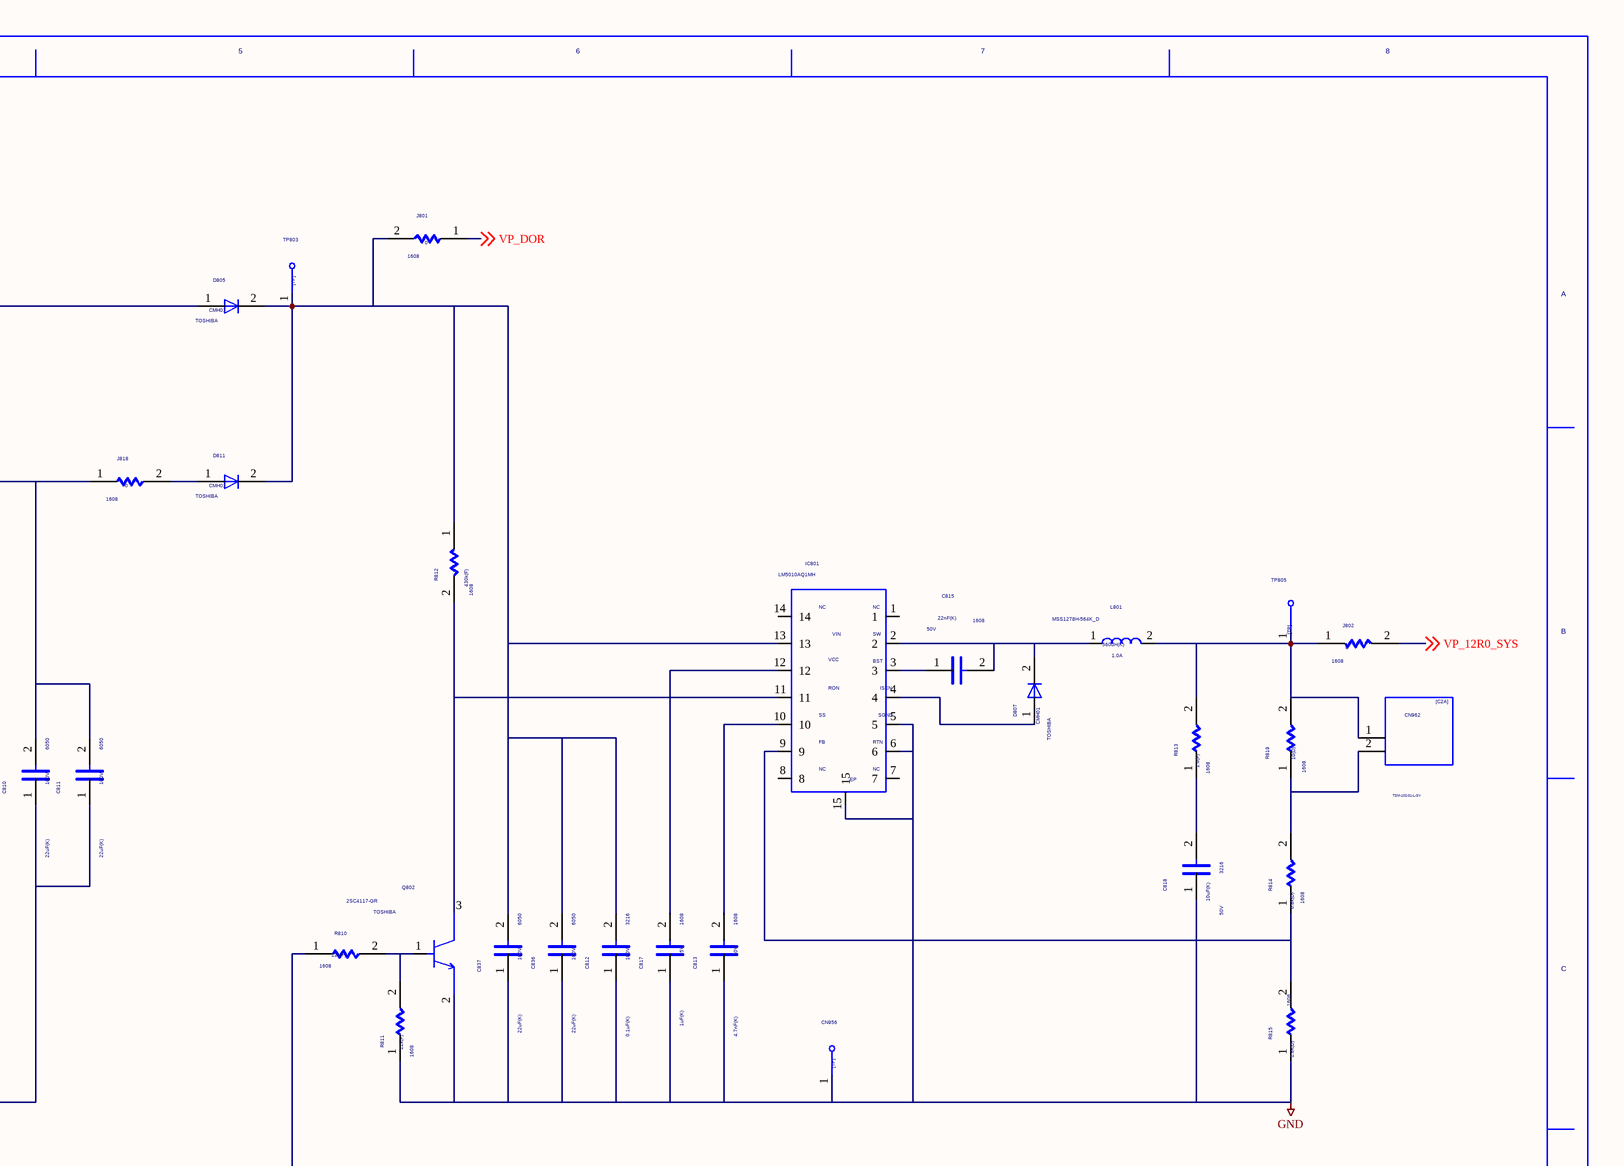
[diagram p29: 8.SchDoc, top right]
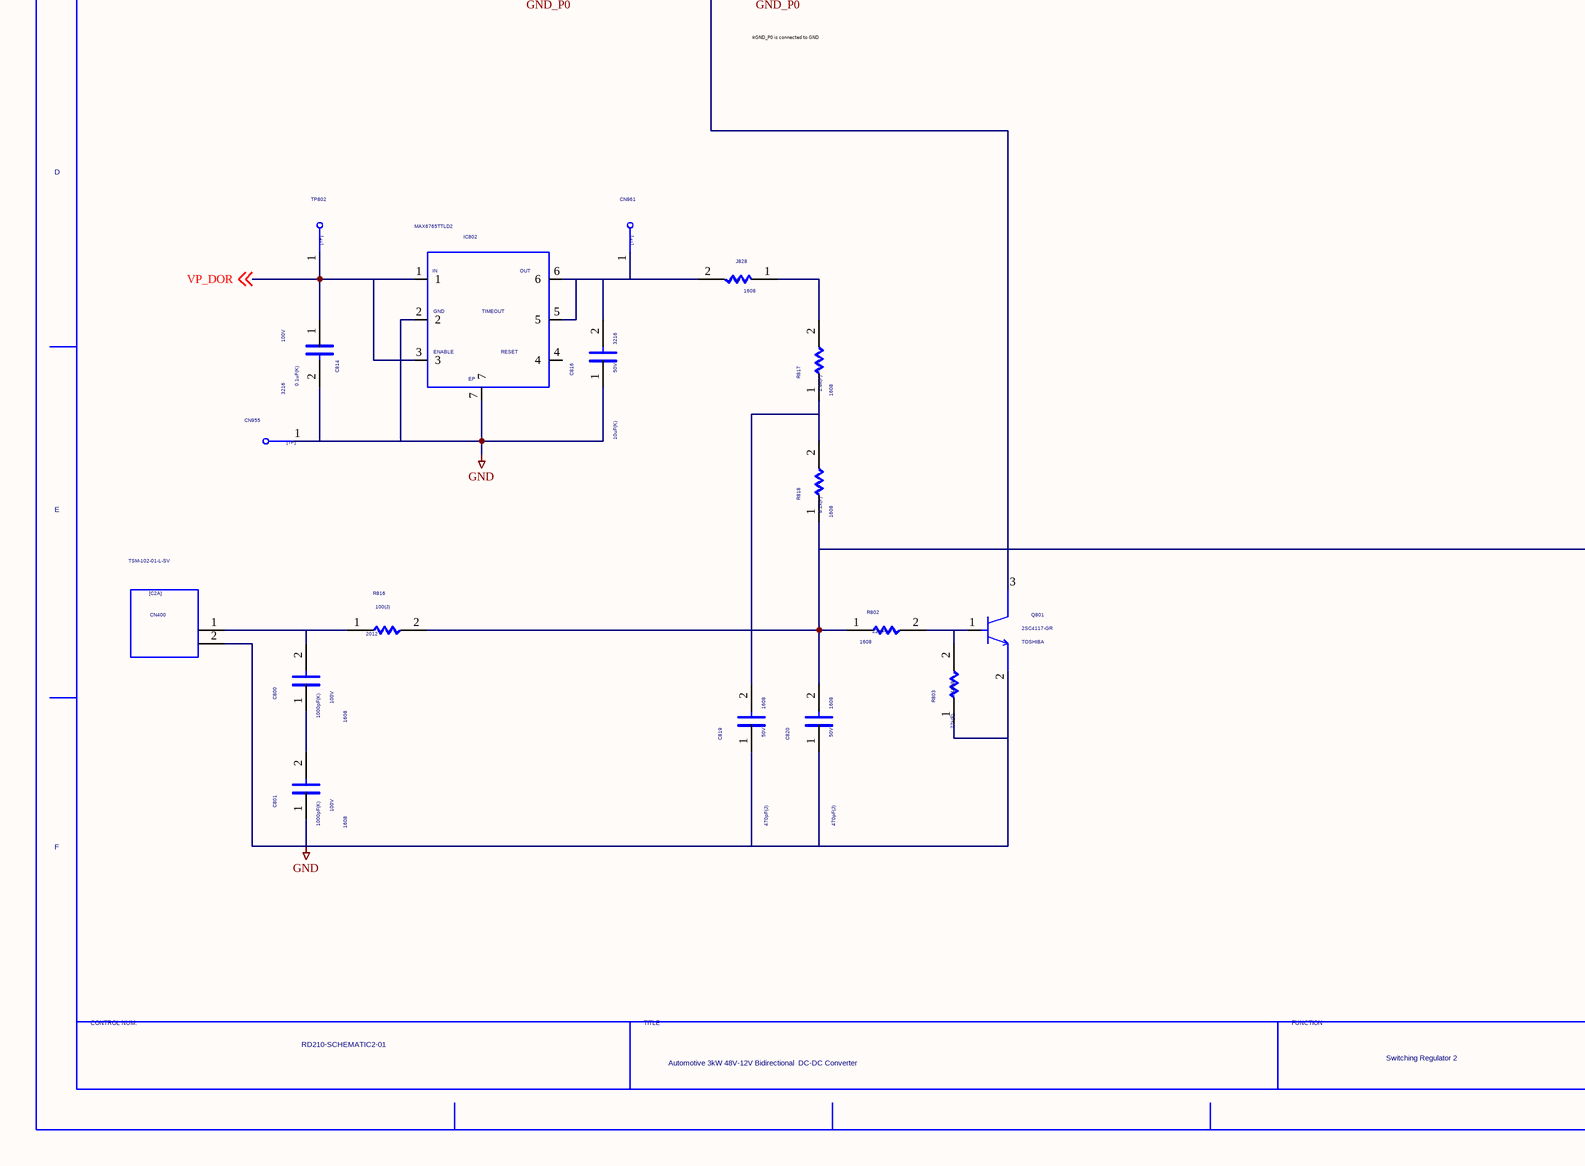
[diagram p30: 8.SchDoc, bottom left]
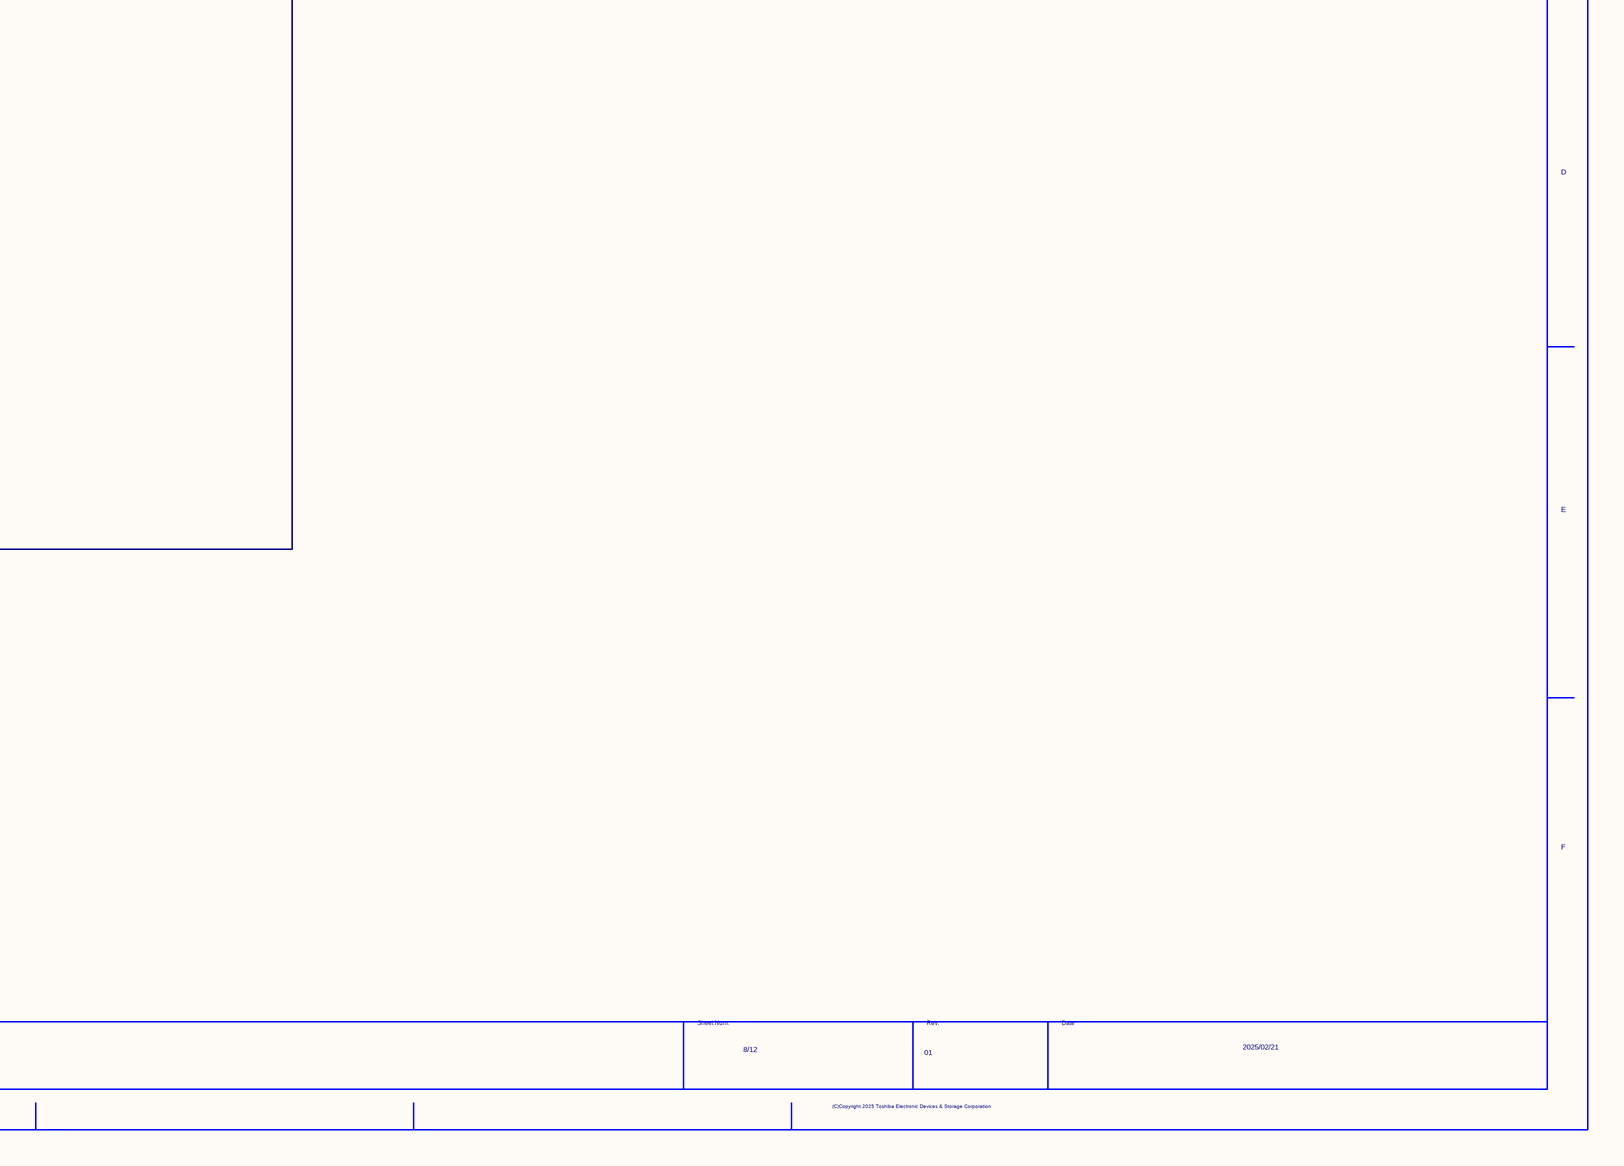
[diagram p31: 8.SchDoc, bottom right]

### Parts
(Parts that share a designator on the sheet are numbered #1, #2 ... from top to bottom, then left to right.)
C800  VAL1: 1000pF(K)  VAL2: 100V  SIZECODESMD: 1608  (hidden comment: C)
C801  VAL1: 1000pF(K)  VAL2: 100V  SIZECODESMD: 1608  (hidden comment: C)
C802  VAL1: 1uF(K)  VAL2: 50V  SIZECODESMD: 2012  (hidden comment: C)
C803  VAL1: 1uF(K)  VAL2: 50V  SIZECODESMD: 2012  (hidden comment: C)
C804  VAL1: 0.1uF(K)  VAL2: 50V  SIZECODESMD: 1608  (hidden comment: C)
C805  VAL1: 10nF(K)  VAL2: 50V  SIZECODESMD: 1608  (hidden comment: C)
C806  VAL1: 22pF(J)  VAL2: 50V  SIZECODESMD: 1608  (hidden comment: C)
C807  VAL1: 15nF(K)  VAL2: 50V  SIZECODESMD: 1608  (hidden comment: C)
C808  VAL1: 10uF(K)  VAL2: 50V  SIZECODESMD: 3216  (hidden comment: C)
C809  VAL1: 1uF(K)  VAL2: 50V  SIZECODESMD: 2012  (hidden comment: C)
C810  VAL1: 22uF(K)  VAL2: 100V  SIZECODESMD: 6050  (hidden comment: C)
C811  VAL1: 22uF(K)  VAL2: 100V  SIZECODESMD: 6050  (hidden comment: C)
C812  VAL1: 0.1uF(K)  VAL2: 100V  SIZECODESMD: 3216  (hidden comment: C)
C813  VAL1: 4.7nF(K)  VAL2: 50V  SIZECODESMD: 1608  (hidden comment: C)
C814  VAL1: 0.1uF(K)  VAL2: 100V  SIZECODESMD: 3216  (hidden comment: C)
C815  VAL1: 22nF(K)  VAL2: 50V  SIZECODESMD: 1608  (hidden comment: C)
C816  VAL1: 10uF(K)  VAL2: 50V  SIZECODESMD: 3216  (hidden comment: C)
C817  VAL1: 1uF(K)  VAL2: 25V  SIZECODESMD: 1608  (hidden comment: C)
C818  VAL1: 10uF(K)  VAL2: 50V  SIZECODESMD: 3216  (hidden comment: C)
C819  VAL1: 470pF(J)  VAL2: 50V  SIZECODESMD: 1608  (hidden comment: C)
C820  VAL1: 470pF(J)  VAL2: 50V  SIZECODESMD: 1608  (hidden comment: C)
C836  VAL1: 22uF(K)  VAL2: 100V  SIZECODESMD: 6050  (hidden comment: C)
C837  VAL1: 22uF(K)  VAL2: 100V  SIZECODESMD: 6050  (hidden comment: C)
CN6  VAL3: B2B-XH-A  (hidden comment: C2A)
CN7  VAL3: B3B-XH-A  (hidden comment: C3A)
CN400  VAL3: TSM-102-01-L-SV  (hidden comment: C2A)
CN945  VAL3: TSM-102-01-L-SV  (hidden comment: C2A)
CN952  TP  (value not drawn)
CN953  TP  (value not drawn)
CN954  TP  (value not drawn)
CN955  TP  (value not drawn)
CN956  TP  (value not drawn)
CN961  TP  (value not drawn)
CN962  VAL3: TSM-102-01-L-SV  (hidden comment: C2A)
D800  USERCOMPTEXT3: TOSHIBA  VAL3: CMH01  (hidden comment: D)
D801  USERCOMPTEXT3: TOSHIBA  VAL3: CMH01  (hidden comment: D)
D802  USERCOMPTEXT3: TOSHIBA  VAL3: CMH01  (hidden comment: D)
D803  USERCOMPTEXT3: TOSHIBA  VAL3: CMH01  (hidden comment: D)
D804  USERCOMPTEXT3: TOSHIBA  VAL3: CMH01  (hidden comment: D)
D805  USERCOMPTEXT3: TOSHIBA  VAL3: CMH01  (hidden comment: D)
D806  USERCOMPTEXT3: TOSHIBA  VAL3: CMH01  (hidden comment: D)
D807  USERCOMPTEXT3: TOSHIBA  VAL3: CMH01  (hidden comment: D)
D808  USERCOMPTEXT3: TOSHIBA  VAL3: CRY82  (hidden comment: ZD)
D809  USERCOMPTEXT3: TOSHIBA  VAL3: 1SS307E  (hidden comment: D)
D810  USERCOMPTEXT3: TOSHIBA  VAL3: 1SS307E  (hidden comment: D)
D811  USERCOMPTEXT3: TOSHIBA  VAL3: CMH01  (hidden comment: D)
IC800  LM5001IDQ1
IC801  LM5010AQ1MH
IC802  MAX6765TTLD2
J801  VAL1: 0  SIZECODESMD: 1608  (hidden comment: R)
J802  VAL1: 0  SIZECODESMD: 1608  (hidden comment: R)
J818  VAL1: 0  SIZECODESMD: 1608  (hidden comment: R)
J828  VAL1: 0  SIZECODESMD: 1608  (hidden comment: R)
L800  VAL1: 33uH(M)  VAL2: 1.1A  VAL3: LAYPH06045DL330MGA  (hidden comment: L)
L801  VAL1: 560uH(K)  VAL2: 1.0A  VAL3: MSS1278H-564K_D  (hidden comment: L)
Q801  USERCOMPTEXT3: TOSHIBA  VAL3: 2SC4117-GR  (hidden comment: TRN)
Q802  USERCOMPTEXT3: TOSHIBA  VAL3: 2SC4117-GR  (hidden comment: TRN)
R800  VAL1: 27k(F)  SIZECODESMD: 1608  (hidden comment: R)
R801  VAL1: 100k(F)  SIZECODESMD: 1608  (hidden comment: R)
R802  VAL1: 22k(F)  SIZECODESMD: 1608  (hidden comment: R)
R803  VAL1: 22k(F)  SIZECODESMD: 1608  (hidden comment: R)
R804  VAL1: 10k(F)  SIZECODESMD: 1608  (hidden comment: R)
R805  VAL1: 18k(F)  SIZECODESMD: 1608  (hidden comment: R)
R806  VAL1: 18k(F)  SIZECODESMD: 1608  (hidden comment: R)
R807  VAL1: 10(J)  SIZECODESMD: 2012  (hidden comment: R)
R808  VAL1: 12k(D)  SIZECODESMD: 1608  (hidden comment: R)
R809  VAL1: 1k(D)  SIZECODESMD: 1608  (hidden comment: R)
R810  VAL1: 22k(F)  SIZECODESMD: 1608  (hidden comment: R)
R811  VAL1: 22k(F)  SIZECODESMD: 1608  (hidden comment: R)
R812  VAL1: 430k(F)  SIZECODESMD: 1608  (hidden comment: R)
R813  VAL1: 1.6(F)  SIZECODESMD: 1608  (hidden comment: R)
R814  VAL1: 6.8k(D)  SIZECODESMD: 1608  (hidden comment: R)
R815  VAL1: 1.8k(D)  SIZECODESMD: 1608  (hidden comment: R)
R816  VAL1: 100(J)  SIZECODESMD: 2012  (hidden comment: R)
R817  VAL1: 1.8k(F)  SIZECODESMD: 1608  (hidden comment: R)
R818  VAL1: 8.2k(F)  SIZECODESMD: 1608  (hidden comment: R)
R819  VAL1: 10(D)  SIZECODESMD: 1608  (hidden comment: R)
R900  VAL1: 10(D)  SIZECODESMD: 1608  (hidden comment: R)
TP801  TP  (value not drawn)
TP802  TP  (value not drawn)
TP803  TP  (value not drawn)
TP805  TP  (value not drawn)
U?#8  DATE: 2025/02/21  DRAWINGNUMBER: RD210-SCHEMATIC2-01  TITLE: Automotive 3kW 48V-12V Bidirectional / DC-DC Converter  FUNCTION: Switching Regulator 2  SHEETNUMBER: 8/12  REVISION: 01  (hidden comment: WAKU_DEF_A3)

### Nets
GND: C801.1 C812.1 C813.1 C814.2 C816.1 C817.1 C818.1 C819.1 C820.1 C836.1 C837.1 CN400.2 CN955.1 CN956.1 IC801.5 IC801.6 IC801.15 IC802.2 IC802.7 Q801.2(E) Q802.2(E) R803.1 R811.1 R815.1
GND_P0: C802.1 C803.1 C804.1 C805.2 C808.1 C809.1 C810.1 C811.1 CN7.3 CN953.1 D808.1(A) IC800.4 R804.2 R805.1 R809.1
VP_H: CN6.1 CN6.2 D805.1(A)
VP_L: CN7.1 D800.1(A)
SIG0083: C817.2 IC801.12
SIG0084: C813.2 IC801.10
SIG0085: D807.1(A) IC801.4
SIG0087: C815.2 D807.2(C) IC801.2 L801.1
SIG00810: C815.1 IC801.3
SIG00814: C809.2 D810.2(C) IC800.3 R801.1
SIG00815: C810.2 C811.2 CN945.1 CN954.1 D806.2(C) J818.1 R900.2
SIG00816: C805.1 D808.2(C) IC800.8 Q801.3(C) R804.1 R806.2
SIG00818: J828.1 R817.2
SIG00819: C820.2 R802.1 R810.1 R816.2 R818.1
SIG946: C802.2 C803.2 D800.2(C) D801.2(C) D802.2(C) D803.2(C) D804.2(C) L800.1 R807.2 TP801.1
SIG947: C804.2 IC800.2 R806.1 R807.1
SIG948: CN952.1 D806.1(A) IC800.1 L800.2
SIG950: IC800.5 R805.2
SIG954: C806.2 C807.2 D809.1(A) IC800.7
SIG955: C807.1 R800.2
SIG957: CN945.2 R808.2 R900.1
SIG960: C812.2 C836.2 C837.2 D805.2(C) D811.2(C) IC801.13 J801.2 R812.1 TP803.1
SIG961: D811.1(A) J818.2
SIG964: C816.2 CN961.1 IC802.5 IC802.6 J828.2
SIG965: Q801.1(B) R802.2 R803.2
SIG967: C819.2 R817.1 R818.2
SIG968: C800.1 C801.2
SIG969: C800.2 CN400.1 R816.1
SIG980: Q802.1(B) R810.2 R811.2
SIG983: IC801.11 Q802.3(C) R812.2
SIG984: C818.2 R813.1
SIG985: IC801.9 R814.1 R815.2
SIG986: CN962.2 R814.2 R819.1
SIG987: CN962.1 J802.1 L801.2 R813.2 R819.2 TP805.1
SIG1395: C806.1 IC800.6 R800.1 R808.1 R809.2
SIG1396: C808.2 D809.2(C) D810.1(A) R801.2
VP_12R0_SYS: J802.2 ; off-sheet VP_12R0_SYS
VP_DOR: C814.1 IC802.1 IC802.3 J801.1 TP802.1 ; off-sheet VP_DOR
VP_L_0: D801.1(A) ; off-sheet VP_L_0
VP_L_1: D802.1(A) ; off-sheet VP_L_1
VP_L_2: D803.1(A) ; off-sheet VP_L_2
VP_L_3: D804.1(A) ; off-sheet VP_L_3

Not connected (* = marked no-connect by the designer): CN7 2; IC801 1 7 8 14; IC802 4

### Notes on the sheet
- ※CN6 is connected to CN6 of RD210-SCHEMATIC1
- ※CN7 is connected to CN7 of RD210-SCHEMATIC1
- ※GND_P0 is connected to GND

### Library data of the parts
C800-C820 C836 C837 = C: OriginalSymbolOrigin: (2540,7620)
CN6 CN400 CN945 CN962 = C2A: SAVEAREA0: -4611,-206,24632,18258; SAVECOUNT: 25; TIME: 13:28:28; UPDATEUSER: tomizawa-y; UPDATETIME: 12:08:31; OriginalSymbolOrigin: (2540,15240); CDBNAME: CN
CN7 = C3A: SAVEAREA0: -6798,-236,26764,20869; TIME: 09:53:04; UPDATEUSER: tomizawa-y; UPDATETIME: 09:53:12; SAVECOUNT: 2; OriginalSymbolOrigin: (2540,17780); CDBNAME: CN
CN952-CN956 CN961 = TP: as CN957 on sheet 6
D800-D807 D809-D811 = D: SAVEAREA0: -225,-91,12804,7836; SAVECOUNT: 3; TIME: 14:49:55; UPDATEUSER: 19870035; UPDATETIME: 14:20:16; OriginalSymbolOrigin: (5080,5080)
D808 = ZD: SAVEAREA0: -4630,-153,17114,13055; TIME: 14:49:55; UPDATEUSER: fukuda-y; UPDATETIME: 08:18:42; SAVECOUNT: 6; OriginalSymbolOrigin: (5080,5080); CDBNAME: D
IC800 = LM5001IDQ1: MANUFACTURER: Panasonic; ITEM: Register; SIZECODESMD: 1608; VLUE4: (B); TIME: 08:44:47; UPDATEUSER: sptcae13; UPDATETIME: 14:02:03; SAVECOUNT: 4; SAVEAREA0: -6176,-15431,28749,482; OriginalSymbolOrigin: (2540,0); CDBNAME: IC
IC801 = LM5010AQ1MH: MANUFACTURER: MURATA; ITEM: CAP Ceramic; SIZECODESMD: 1005; VALUE4: X7R; TIME: 08:44:45; UPDATEUSER: sptcae13; UPDATETIME: 15:58:38; SAVECOUNT: 5; SAVEAREA0: -56454,-69958,102754,17159; OriginalSymbolOrigin: (2540,0); CDBNAME: IC
IC802 = MAX6765TTLD2: MANUFACTURER: Panasonic; ITEM: Register; SIZECODESMD: 1608; VLUE4: (B); TIME: 08:44:47; UPDATEUSER: t4887876; UPDATETIME: 18:30:10; SAVECOUNT: 8; SAVEAREA0: -27917,-34385,50659,1418; OriginalSymbolOrigin: (2540,0); CDBNAME: IC
J801 J802 J818 J828 = R: as J803 on sheet 6
L800 L801 = L: OriginalSymbolOrigin: (2540,5080)
Q801 Q802 = TRN: TIME: 09:39:04; UPDATEUSER: 19910145; UPDATETIME: 15:12:10; SAVECOUNT: 8; SAVEAREA0: -6194,-158,18648,15662; OriginalSymbolOrigin: (2540,17780); CDBNAME: Q
R800 R801 R804-R806 R808 R809 R812 R814 R815 = R: as R660 on sheet 6
R802 R803 R810 R811 R813 R817 R818 = R: VAL2: 333mW; OriginalSymbolOrigin: (5080,5080)
R807 = R: VAL2: 500mW; OriginalSymbolOrigin: (5080,5080)
R816 = R: VAL2: 250mW; OriginalSymbolOrigin: (5080,5080)
R819 R900 = R: VAL2: 100mW; OriginalSymbolOrigin: (5080,5080)
TP801 TP802 TP805 = TP: as TP806 on sheet 6
TP803 = TP: TIME: 16:12:21; UPDATEUSER: fukuda-y; UPDATETIME: 16:18:11; SAVECOUNT: 2; SAVEAREA0: -242,-92,12810,7836; OriginalSymbolOrigin: (0,7620); VAL3: TSW-101-07-G-S
U?#8 = WAKU_DEF_A3: PLOTTIME: HH:MM; SAVEAREA0: 96913,-567914,509243,-368858; TIME: 14:30:25; UPDATEUSER: t5459927; UPDATETIME: 09:54:20; SAVECOUNT: 19; ZONEOFFSETX: 36; ZONEOFFSETY: -24; OriginalSymbolOrigin: (12700,-12700); SHTSAVECOUNT: 97

## Sheet 9.SchDoc
size 609 x 444 mm
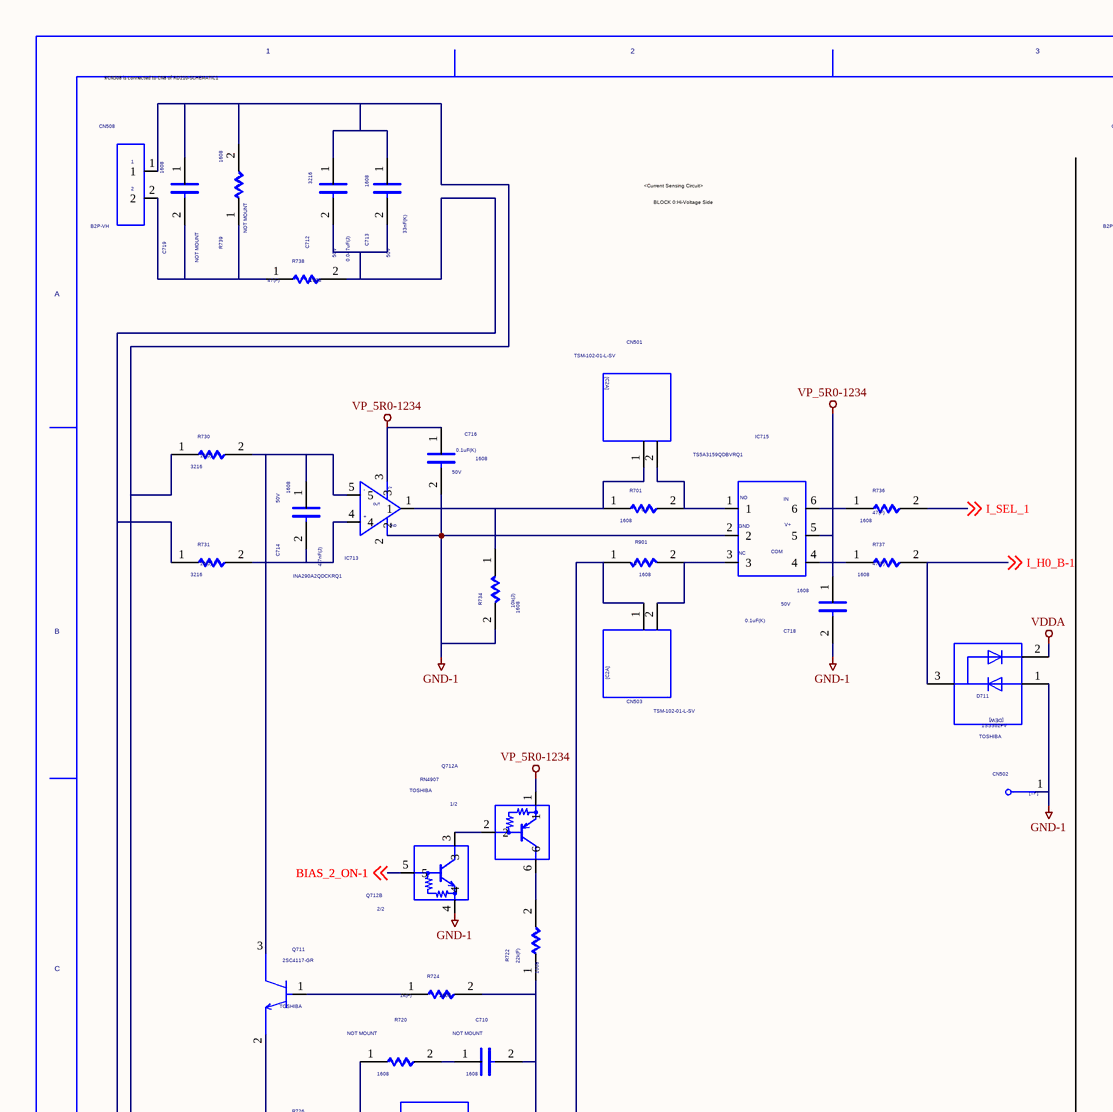
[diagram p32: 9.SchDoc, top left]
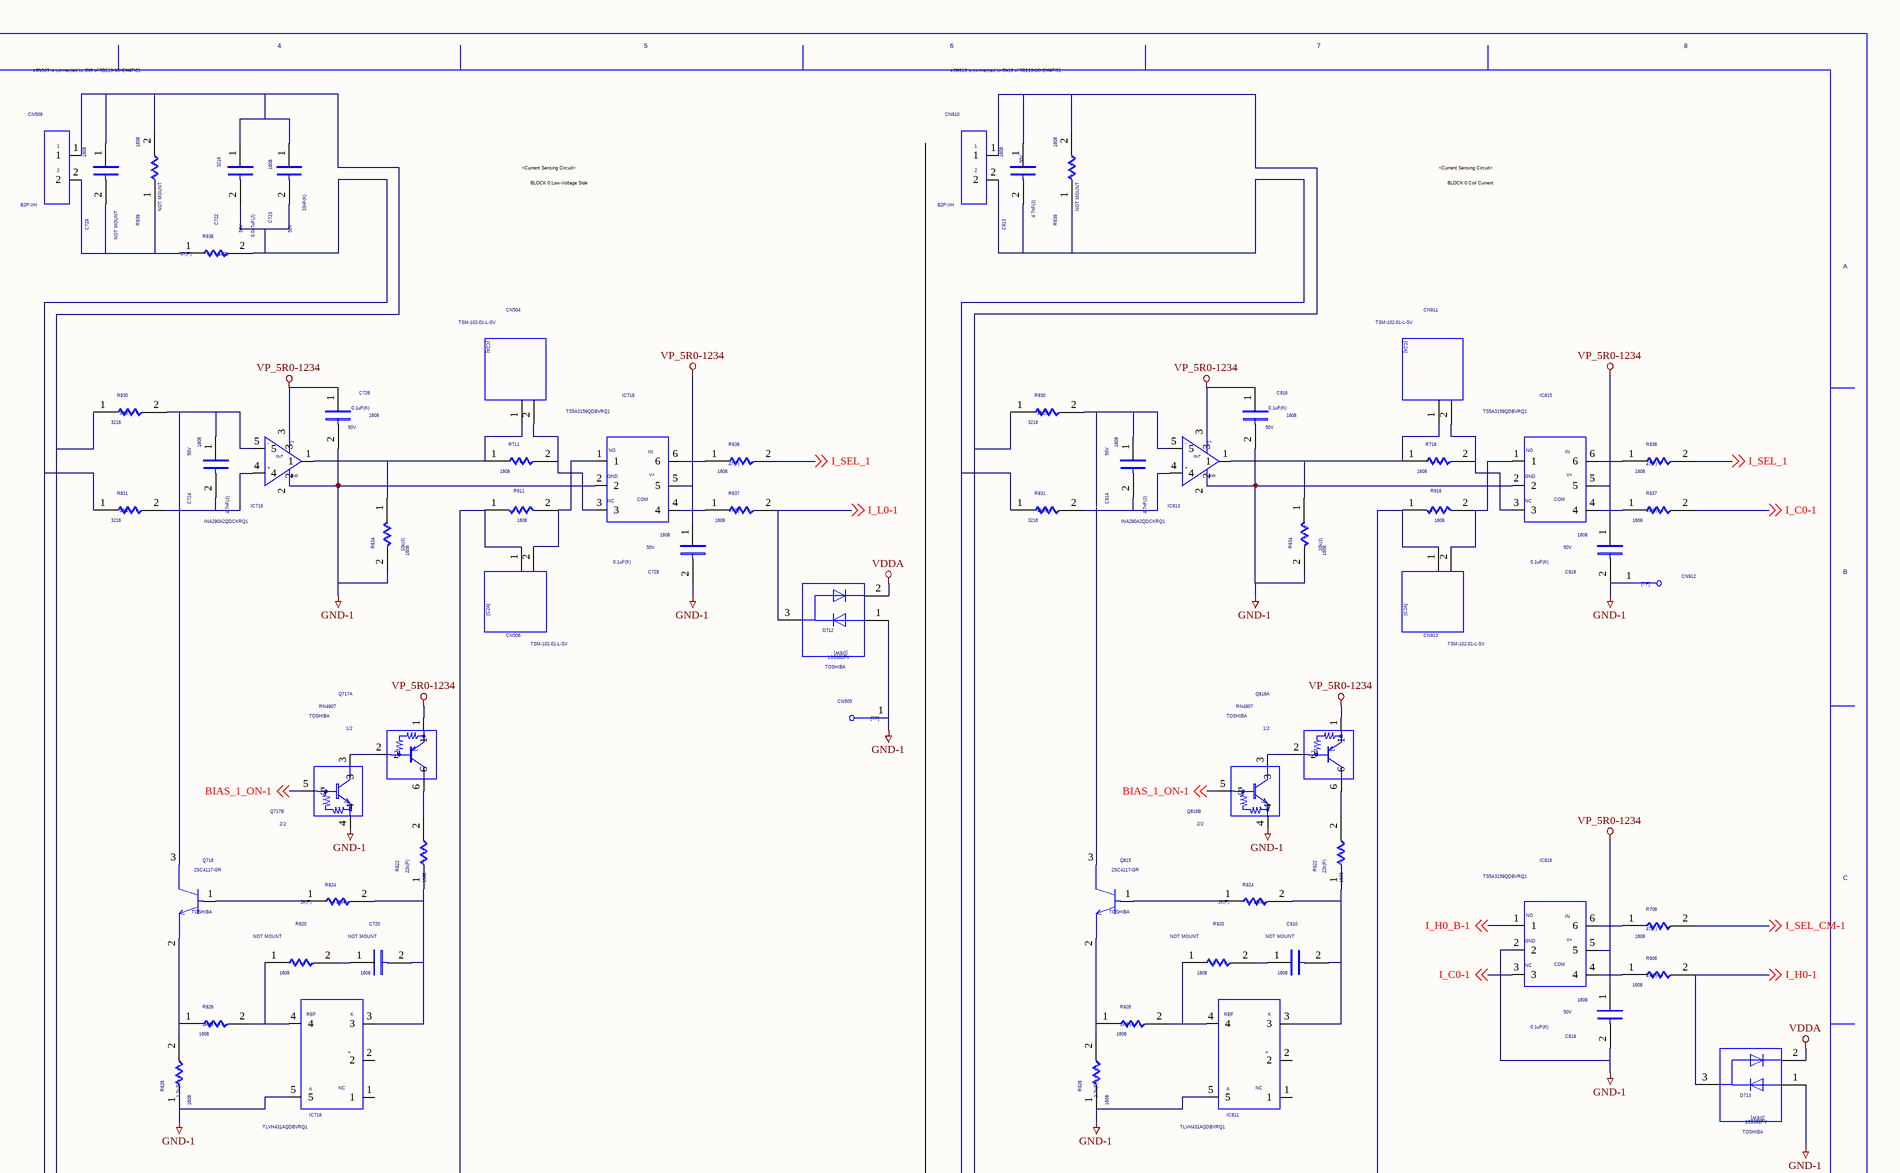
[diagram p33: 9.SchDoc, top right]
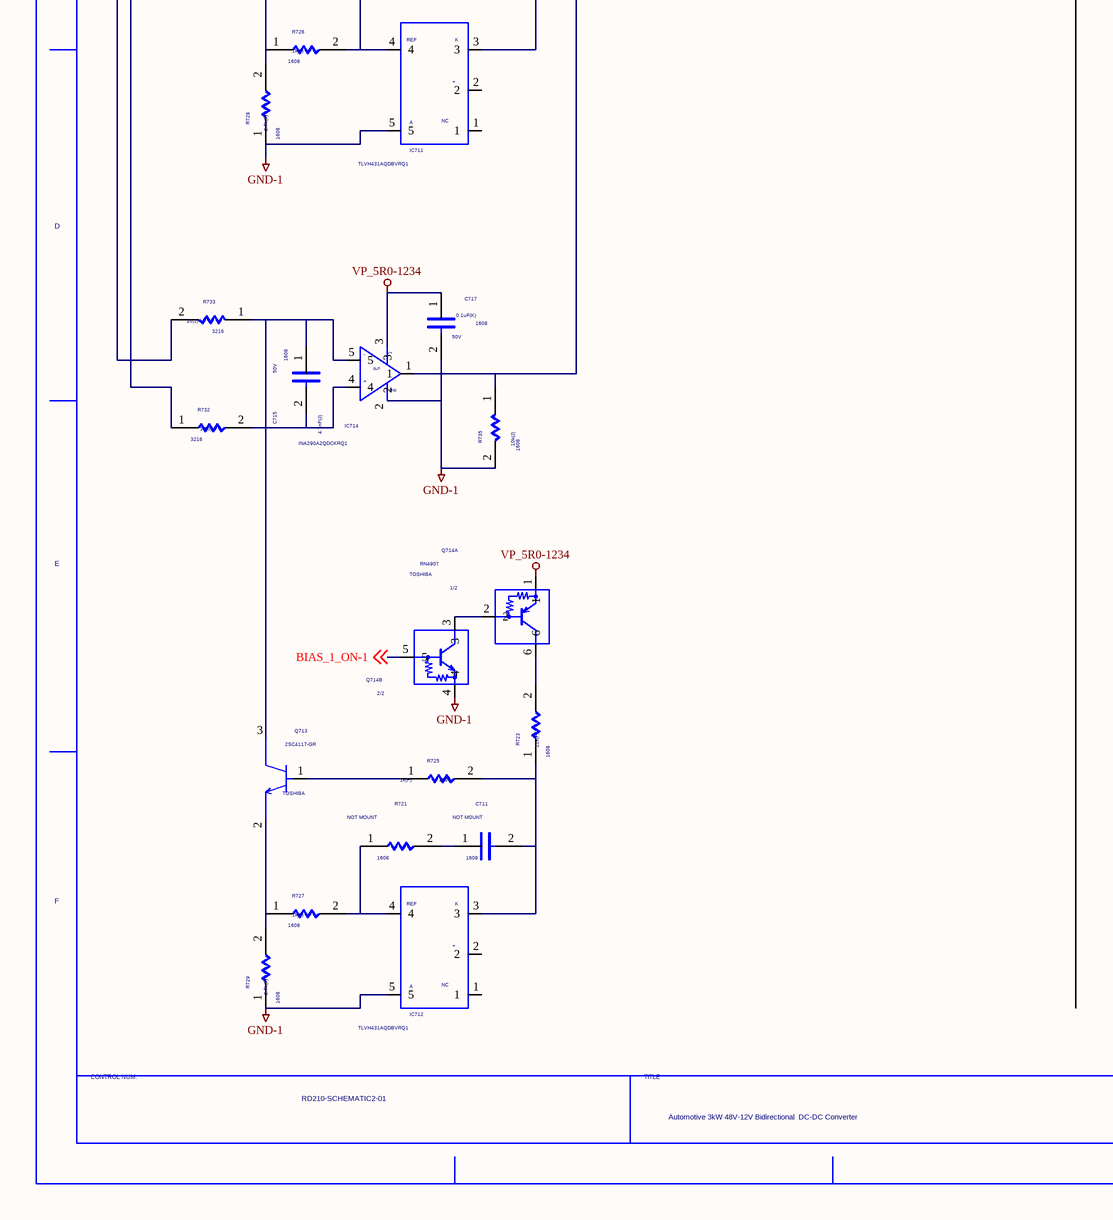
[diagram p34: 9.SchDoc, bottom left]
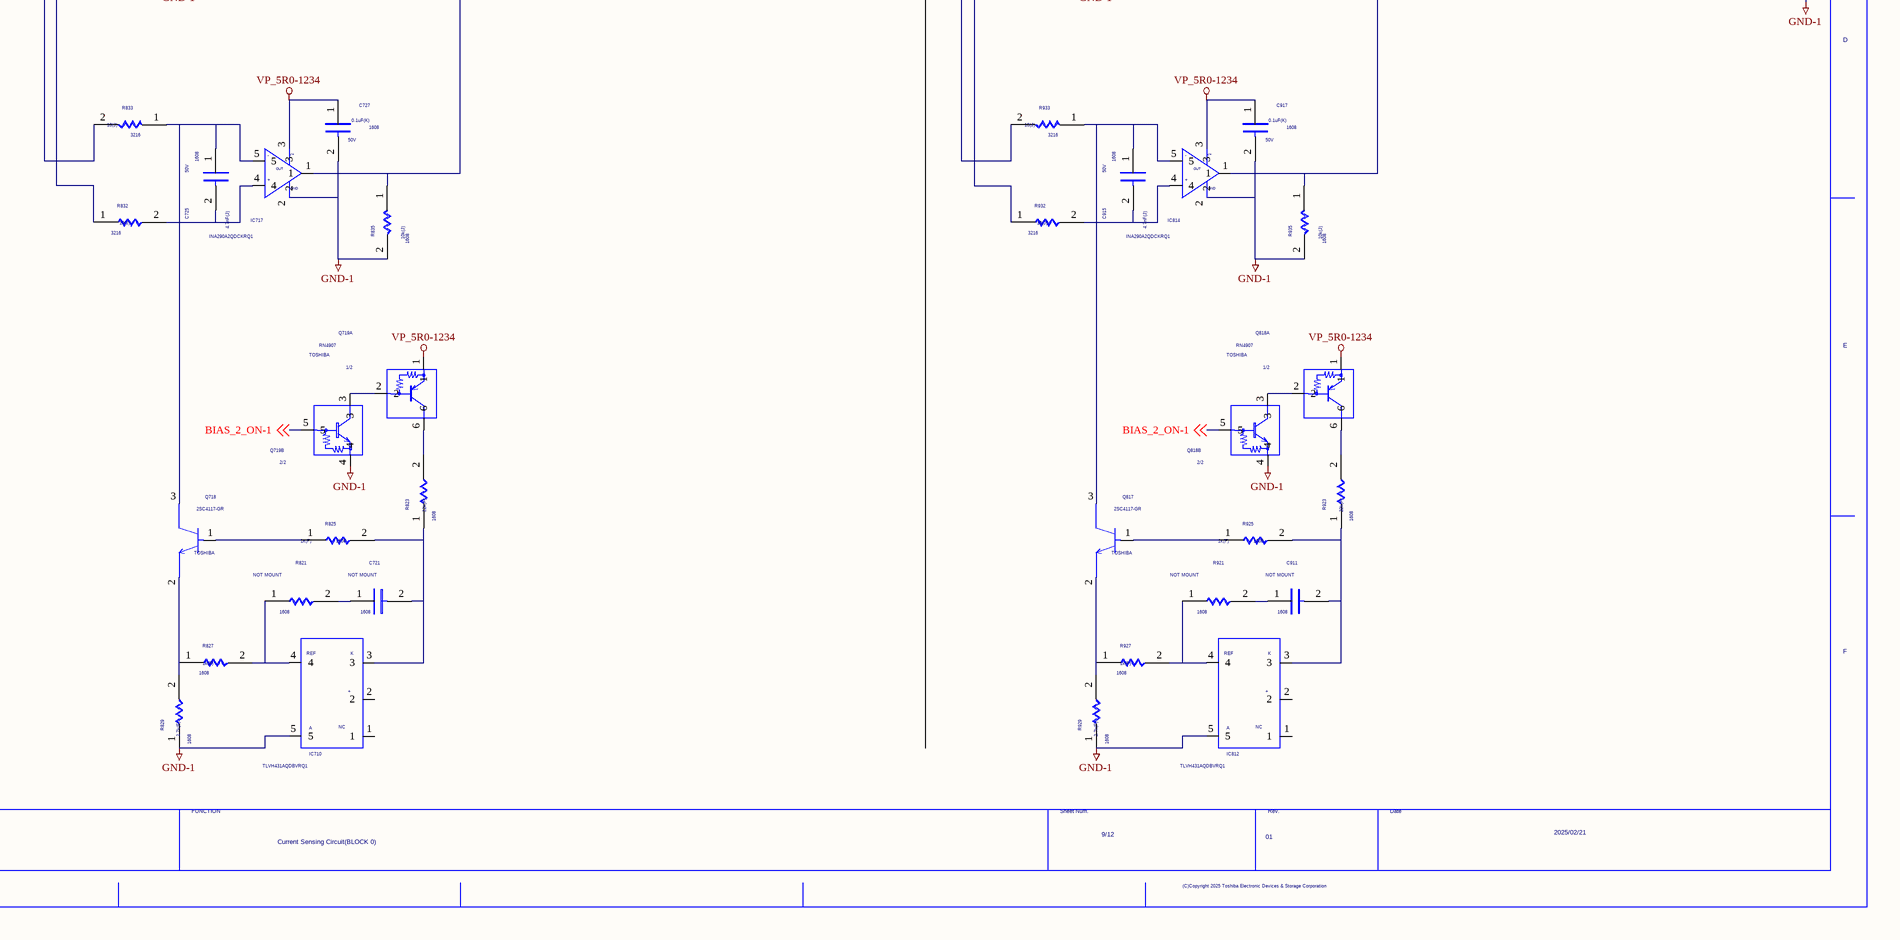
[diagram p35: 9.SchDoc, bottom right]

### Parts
(Parts that share a designator on the sheet are numbered #1, #2 ... from top to bottom, then left to right.)
C710  NOTMOUNT: NOT MOUNT  SIZECODESMD: 1608  (hidden comment: C)
C711  NOTMOUNT: NOT MOUNT  SIZECODESMD: 1608  (hidden comment: C)
C712  VAL1: 0.047uF(J)  VAL2: 50V  SIZECODESMD: 3216  (hidden comment: C)
C713  VAL1: 33nF(K)  VAL2: 50V  SIZECODESMD: 1608  (hidden comment: C)
C714  VAL1: 4.7nF(J)  VAL2: 50V  SIZECODESMD: 1608  (hidden comment: C)
C715  VAL1: 4.7nF(J)  VAL2: 50V  SIZECODESMD: 1608  (hidden comment: C)
C716  VAL1: 0.1uF(K)  VAL2: 50V  SIZECODESMD: 1608  (hidden comment: C)
C717  VAL1: 0.1uF(K)  VAL2: 50V  SIZECODESMD: 1608  (hidden comment: C)
C718  VAL1: 0.1uF(K)  VAL2: 50V  SIZECODESMD: 1608  (hidden comment: C)
C719  NOTMOUNT: NOT MOUNT  SIZECODESMD: 1608  (hidden comment: C)
C720  NOTMOUNT: NOT MOUNT  SIZECODESMD: 1608  (hidden comment: C)
C721  NOTMOUNT: NOT MOUNT  SIZECODESMD: 1608  (hidden comment: C)
C722  VAL1: 0.047uF(J)  VAL2: 50V  SIZECODESMD: 3216  (hidden comment: C)
C723  VAL1: 33nF(K)  VAL2: 50V  SIZECODESMD: 1608  (hidden comment: C)
C724  VAL1: 4.7nF(J)  VAL2: 50V  SIZECODESMD: 1608  (hidden comment: C)
C725  VAL1: 4.7nF(J)  VAL2: 50V  SIZECODESMD: 1608  (hidden comment: C)
C726  VAL1: 0.1uF(K)  VAL2: 50V  SIZECODESMD: 1608  (hidden comment: C)
C727  VAL1: 0.1uF(K)  VAL2: 50V  SIZECODESMD: 1608  (hidden comment: C)
C728  VAL1: 0.1uF(K)  VAL2: 50V  SIZECODESMD: 1608  (hidden comment: C)
C729  NOTMOUNT: NOT MOUNT  SIZECODESMD: 1608  (hidden comment: C)
C910  NOTMOUNT: NOT MOUNT  SIZECODESMD: 1608  (hidden comment: C)
C911  NOTMOUNT: NOT MOUNT  SIZECODESMD: 1608  (hidden comment: C)
C913  VAL1: 4.7nF(J)  VAL2: 50V  SIZECODESMD: 1608  (hidden comment: C)
C914  VAL1: 4.7nF(J)  VAL2: 50V  SIZECODESMD: 1608  (hidden comment: C)
C915  VAL1: 4.7nF(J)  VAL2: 50V  SIZECODESMD: 1608  (hidden comment: C)
C916  VAL1: 0.1uF(K)  VAL2: 50V  SIZECODESMD: 1608  (hidden comment: C)
C917  VAL1: 0.1uF(K)  VAL2: 50V  SIZECODESMD: 1608  (hidden comment: C)
C918  VAL1: 0.1uF(K)  VAL2: 50V  SIZECODESMD: 1608  (hidden comment: C)
C919  VAL1: 0.1uF(K)  VAL2: 50V  SIZECODESMD: 1608  (hidden comment: C)
CN501  VAL3: TSM-102-01-L-SV  (hidden comment: C2A)
CN502  TP  (value not drawn)
CN503  VAL3: TSM-102-01-L-SV  (hidden comment: C2A)
CN504  VAL3: TSM-102-01-L-SV  (hidden comment: C2A)
CN505  TP  (value not drawn)
CN506  VAL3: TSM-102-01-L-SV  (hidden comment: C2A)
CN508  B2P-VH
CN509  B2P-VH
CN910  B2P-VH
CN911  VAL3: TSM-102-01-L-SV  (hidden comment: C2A)
CN912  TP  (value not drawn)
CN913  VAL3: TSM-102-01-L-SV  (hidden comment: C2A)
D711  USERCOMPTEXT3: TOSHIBA  VAL3: 1SS362FV  (hidden comment: DEW)
D712  USERCOMPTEXT3: TOSHIBA  VAL3: 1SS362FV  (hidden comment: DEW)
D713  USERCOMPTEXT3: TOSHIBA  VAL3: 1SS362FV  (hidden comment: DEW)
IC710  TLVH431AQDBVRQ1
IC711  TLVH431AQDBVRQ1
IC712  TLVH431AQDBVRQ1
IC713  INA290A2QDCKRQ1
IC714  INA290A2QDCKRQ1
IC715  TS5A3159QDBVRQ1
IC716  INA290A2QDCKRQ1
IC717  INA290A2QDCKRQ1
IC718  TS5A3159QDBVRQ1
IC719  TLVH431AQDBVRQ1
IC811  TLVH431AQDBVRQ1
IC812  TLVH431AQDBVRQ1
IC813  INA290A2QDCKRQ1
IC814  INA290A2QDCKRQ1
IC815  TS5A3159QDBVRQ1
IC816  TS5A3159QDBVRQ1
Q711  USERCOMPTEXT3: TOSHIBA  VAL3: 2SC4117-GR  (hidden comment: TRN)
Q712  USERCOMPTEXT1: 1/2  USERCOMPTEXT3: TOSHIBA  VAL3: RN4907  (hidden comment: RN4907_Q2)  (parts A,B of 2)
Q713  USERCOMPTEXT3: TOSHIBA  VAL3: 2SC4117-GR  (hidden comment: TRN)
Q714  USERCOMPTEXT1: 1/2  USERCOMPTEXT3: TOSHIBA  VAL3: RN4907  (hidden comment: RN4907_Q2)  (parts A,B of 2)
Q716  USERCOMPTEXT3: TOSHIBA  VAL3: 2SC4117-GR  (hidden comment: TRN)
Q717  USERCOMPTEXT1: 1/2  USERCOMPTEXT3: TOSHIBA  VAL3: RN4907  (hidden comment: RN4907_Q2)  (parts A,B of 2)
Q718  USERCOMPTEXT3: TOSHIBA  VAL3: 2SC4117-GR  (hidden comment: TRN)
Q719  USERCOMPTEXT1: 1/2  USERCOMPTEXT3: TOSHIBA  VAL3: RN4907  (hidden comment: RN4907_Q2)  (parts A,B of 2)
Q815  USERCOMPTEXT3: TOSHIBA  VAL3: 2SC4117-GR  (hidden comment: TRN)
Q816  USERCOMPTEXT1: 1/2  USERCOMPTEXT3: TOSHIBA  VAL3: RN4907  (hidden comment: RN4907_Q2)  (parts A,B of 2)
Q817  USERCOMPTEXT3: TOSHIBA  VAL3: 2SC4117-GR  (hidden comment: TRN)
Q818  USERCOMPTEXT1: 1/2  USERCOMPTEXT3: TOSHIBA  VAL3: RN4907  (hidden comment: RN4907_Q2)  (parts A,B of 2)
R701  VAL1: 0  SIZECODESMD: 1608  (hidden comment: R)
R706  VAL1: 47(F)  SIZECODESMD: 1608  (hidden comment: R)
R711  VAL1: 0  SIZECODESMD: 1608  (hidden comment: R)
R716  VAL1: 0  SIZECODESMD: 1608  (hidden comment: R)
R720  NOTMOUNT: NOT MOUNT  SIZECODESMD: 1608  (hidden comment: R)
R721  NOTMOUNT: NOT MOUNT  SIZECODESMD: 1608  (hidden comment: R)
R722  VAL1: 22k(F)  SIZECODESMD: 1608  (hidden comment: R)
R723  VAL1: 22k(F)  SIZECODESMD: 1608  (hidden comment: R)
R724  VAL1: 1k(F)  SIZECODESMD: 1608  (hidden comment: R)
R725  VAL1: 1k(F)  SIZECODESMD: 1608  (hidden comment: R)
R726  VAL1: 1k(F)  SIZECODESMD: 1608  (hidden comment: R)
R727  VAL1: 1k(F)  SIZECODESMD: 1608  (hidden comment: R)
R728  VAL1: 2.7k(F)  SIZECODESMD: 1608  (hidden comment: R)
R729  VAL1: 2.7k(F)  SIZECODESMD: 1608  (hidden comment: R)
R730  VAL1: 10(J)  SIZECODESMD: 3216  (hidden comment: R)
R731  VAL1: 10(J)  SIZECODESMD: 3216  (hidden comment: R)
R732  VAL1: 10(J)  SIZECODESMD: 3216  (hidden comment: R)
R733  VAL1: 10(J)  SIZECODESMD: 3216  (hidden comment: R)
R734  VAL1: 10k(J)  SIZECODESMD: 1608  (hidden comment: R)
R735  VAL1: 10k(J)  SIZECODESMD: 1608  (hidden comment: R)
R736  VAL1: 47(F)  SIZECODESMD: 1608  (hidden comment: R)
R737  VAL1: 47(F)  SIZECODESMD: 1608  (hidden comment: R)
R738  VAL1: 47(F)  SIZECODESMD: 1608  (hidden comment: R)
R739  NOTMOUNT: NOT MOUNT  SIZECODESMD: 1608  (hidden comment: R)
R820  NOTMOUNT: NOT MOUNT  SIZECODESMD: 1608  (hidden comment: R)
R821  NOTMOUNT: NOT MOUNT  SIZECODESMD: 1608  (hidden comment: R)
R822  VAL1: 22k(F)  SIZECODESMD: 1608  (hidden comment: R)
R823  VAL1: 22k(F)  SIZECODESMD: 1608  (hidden comment: R)
R824  VAL1: 1k(F)  SIZECODESMD: 1608  (hidden comment: R)
R825  VAL1: 1k(F)  SIZECODESMD: 1608  (hidden comment: R)
R826  VAL1: 1k(F)  SIZECODESMD: 1608  (hidden comment: R)
R827  VAL1: 1k(F)  SIZECODESMD: 1608  (hidden comment: R)
R828  VAL1: 2.7k(F)  SIZECODESMD: 1608  (hidden comment: R)
R829  VAL1: 2.7k(F)  SIZECODESMD: 1608  (hidden comment: R)
R830  VAL1: 10(J)  SIZECODESMD: 3216  (hidden comment: R)
R831  VAL1: 10(J)  SIZECODESMD: 3216  (hidden comment: R)
R832  VAL1: 10(J)  SIZECODESMD: 3216  (hidden comment: R)
R833  VAL1: 10(J)  SIZECODESMD: 3216  (hidden comment: R)
R834  VAL1: 10k(J)  SIZECODESMD: 1608  (hidden comment: R)
R835  VAL1: 10k(J)  SIZECODESMD: 1608  (hidden comment: R)
R836  VAL1: 47(F)  SIZECODESMD: 1608  (hidden comment: R)
R837  VAL1: 47(F)  SIZECODESMD: 1608  (hidden comment: R)
R838  VAL1: 47(F)  SIZECODESMD: 1608  (hidden comment: R)
R839  NOTMOUNT: NOT MOUNT  SIZECODESMD: 1608  (hidden comment: R)
R901  VAL1: 0  SIZECODESMD: 1608  (hidden comment: R)
R906  VAL1: 47(F)  SIZECODESMD: 1608  (hidden comment: R)
R911  VAL1: 0  SIZECODESMD: 1608  (hidden comment: R)
R916  VAL1: 0  SIZECODESMD: 1608  (hidden comment: R)
R920  NOTMOUNT: NOT MOUNT  SIZECODESMD: 1608  (hidden comment: R)
R921  NOTMOUNT: NOT MOUNT  SIZECODESMD: 1608  (hidden comment: R)
R922  VAL1: 22k(F)  SIZECODESMD: 1608  (hidden comment: R)
R923  VAL1: 22k(F)  SIZECODESMD: 1608  (hidden comment: R)
R924  VAL1: 1k(F)  SIZECODESMD: 1608  (hidden comment: R)
R925  VAL1: 1k(F)  SIZECODESMD: 1608  (hidden comment: R)
R926  VAL1: 1k(F)  SIZECODESMD: 1608  (hidden comment: R)
R927  VAL1: 1k(F)  SIZECODESMD: 1608  (hidden comment: R)
R928  VAL1: 2.7k(F)  SIZECODESMD: 1608  (hidden comment: R)
R929  VAL1: 2.7k(F)  SIZECODESMD: 1608  (hidden comment: R)
R930  VAL1: 10(J)  SIZECODESMD: 3216  (hidden comment: R)
R931  VAL1: 10(J)  SIZECODESMD: 3216  (hidden comment: R)
R932  VAL1: 10(J)  SIZECODESMD: 3216  (hidden comment: R)
R933  VAL1: 10(J)  SIZECODESMD: 3216  (hidden comment: R)
R934  VAL1: 10k(J)  SIZECODESMD: 1608  (hidden comment: R)
R935  VAL1: 10k(J)  SIZECODESMD: 1608  (hidden comment: R)
R936  VAL1: 47(F)  SIZECODESMD: 1608  (hidden comment: R)
R937  VAL1: 47(F)  SIZECODESMD: 1608  (hidden comment: R)
R939  NOTMOUNT: NOT MOUNT  SIZECODESMD: 1608  (hidden comment: R)
U?#9  DATE: 2025/02/21  DRAWINGNUMBER: RD210-SCHEMATIC2-01  TITLE: Automotive 3kW 48V-12V Bidirectional / DC-DC Converter  FUNCTION: Current Sensing Circuit(BLOCK 0)  SHEETNUMBER: 9/12  REVISION: 01  (hidden comment: WAKU_DEF_A3)

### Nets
GND-1: C716.2 C717.2 C718.2 C726.2 C727.2 C728.2 C916.2 C917.2 C918.2 C919.2 CN502.1 CN505.1 CN912.1 D711.1(A) D712.1(A) D713.1(A) IC710.5 IC711.5 IC712.5 IC713.2 IC714.2 IC715.2 IC716.2 IC717.2 IC718.2 IC719.5 IC811.5 IC812.5 IC813.2 IC814.2 IC815.2 IC816.2 Q712.4 Q714.4 Q717.4 Q719.4 Q816.4 Q818.4 R728.1 R729.1 R734.2 R735.2 R828.1 R829.1 R834.2 R835.2 R928.1 R929.1 R934.2 R935.2
VDDA: D711.2(C) D712.2(C) D713.2(C)
VP_5R0-1234: C716.1 C717.1 C718.1 C726.1 C727.1 C728.1 C916.1 C917.1 C918.1 C919.1 IC713.3 IC714.3 IC715.5 IC716.3 IC717.3 IC718.5 IC813.3 IC814.3 IC815.5 IC816.5 Q712.1 Q714.1 Q717.1 Q719.1 Q816.1 Q818.1
BIAS_1_ON-1: Q714.5 Q717.5 Q816.5 ; off-sheet BIAS_1_ON-1
BIAS_2_ON-1: Q712.5 Q719.5 Q818.5 ; off-sheet BIAS_2_ON-1
I_C0-1: IC816.3 R937.2 ; off-sheet I_C0-1
I_H0-1: D713.3(AC) R906.2 ; off-sheet I_H0-1
I_H0_B-1: D711.3(AC) IC816.1 R737.2 ; off-sheet I_H0_B-1
I_L0-1: D712.3(AC) R837.2 ; off-sheet I_L0-1
I_SEL_1: R736.2 R836.2 R936.2 ; off-sheet I_SEL_1
I_SEL_CM-1: R706.2 ; off-sheet I_SEL_CM-1
SIG0093: C712.1 C713.1 C719.1 CN508.1 R730.1 R732.1 R739.2
SIG0096: CN503.2 IC715.3 R901.2
SIG0099: Q711.2(E) R726.1 R728.2
SIG00911: Q711.1(B) R724.1
SIG00913: C710.1 R720.2
SIG00915: C715.2 IC714.4 R732.2
SIG00919: C719.2 CN508.2 R738.1 R739.1
SIG00920: C714.2 IC713.4 R731.2
SIG00922: CN501.1 IC713.1 R701.1 R734.1
SIG00923: C714.1 IC713.5 Q711.3(C) R730.2
SIG00924: CN501.2 IC715.1 R701.2
SIG00927: IC711.4 R720.1 R726.2
SIG00930: C710.2 IC711.3 R722.1 R724.2
SIG00941: C712.2 C713.2 R731.1 R733.2 R738.2
SIG00952: IC715.4 R737.1
SIG00953: IC715.6 R736.1
SIG00989: Q712.6 R722.2
SIG009106: CN503.1 IC714.1 R735.1 R901.1
SIG009107: Q712.2 Q712.3
SIG009108: Q714.2 Q714.3
SIG009109: C711.2 IC712.3 R723.1 R725.2
SIG009110: IC712.4 R721.1 R727.2
SIG009111: C711.1 R721.2
SIG009112: Q714.6 R723.2
SIG009114: Q713.2(E) R727.1 R729.2
SIG009115: Q713.1(B) R725.1
SIG009116: C715.1 IC714.5 Q713.3(C) R733.1
SIG009117: CN506.2 IC718.1 R911.2
SIG009118: CN504.1 IC716.1 R711.1 R834.1
SIG009119: IC718.6 R836.1
SIG009120: C721.2 IC710.3 R823.1 R825.2
SIG009121: IC718.4 R837.1
SIG009122: C720.1 R820.2
SIG009123: C725.1 IC717.5 Q718.3(C) R833.1
SIG009124: C724.2 IC716.4 R831.2
SIG009125: CN506.1 IC717.1 R835.1 R911.1
SIG009126: Q716.1(B) R824.1
SIG009127: Q718.1(B) R825.1
SIG009128: Q719.6 R823.2
SIG009129: C721.1 R821.2
SIG009130: IC710.4 R821.1 R827.2
SIG009131: C725.2 IC717.4 R832.2
SIG009132: Q716.2(E) R826.1 R828.2
SIG009133: Q717.2 Q717.3
SIG009134: C720.2 IC719.3 R822.1 R824.2
SIG009135: CN504.2 IC718.3 R711.2
SIG009136: Q719.2 Q719.3
SIG009137: C722.2 C723.2 R831.1 R833.2 R838.2
SIG009138: Q718.2(E) R827.1 R829.2
SIG009139: C729.2 CN509.2 R838.1 R839.1
SIG009140: C724.1 IC716.5 Q716.3(C) R830.2
SIG009141: Q717.6 R822.2
SIG009142: IC719.4 R820.1 R826.2
SIG009143: C722.1 C723.1 C729.1 CN509.1 R830.1 R832.1 R839.2
SIG009144: Q816.2 Q816.3
SIG009145: C910.2 IC811.3 R922.1 R924.2
SIG009146: CN911.2 IC815.3 R716.2
SIG009147: C913.1 CN910.1 R930.1 R932.1 R939.2
SIG009148: Q818.2 Q818.3
SIG009149: C914.1 IC813.5 Q815.3(C) R930.2
SIG009150: Q815.2(E) R926.1 R928.2
SIG009151: Q817.2(E) R927.1 R929.2
SIG009152: Q816.6 R922.2
SIG009153: CN913.2 IC815.1 R916.2
SIG009154: IC811.4 R920.1 R926.2
SIG009155: C915.2 IC814.4 R932.2
SIG009156: C911.1 R921.2
SIG009157: Q817.1(B) R925.1
SIG009158: Q815.1(B) R924.1
SIG009159: CN913.1 IC814.1 R916.1 R935.1
SIG009160: IC812.4 R921.1 R927.2
SIG009161: Q818.6 R923.2
SIG009162: CN911.1 IC813.1 R716.1 R934.1
SIG009163: C914.2 IC813.4 R931.2
SIG009164: IC815.4 R937.1
SIG009165: C915.1 IC814.5 Q817.3(C) R933.1
SIG009166: IC815.6 R936.1
SIG009167: C911.2 IC812.3 R923.1 R925.2
SIG009168: C910.1 R920.2
SIG009169: C913.2 CN910.2 R931.1 R933.2 R939.1
SIG009170: IC816.4 R906.1
SIG009171: IC816.6 R706.1

Not connected (* = marked no-connect by the designer): IC710 1 2; IC711 1 2; IC712 1 2; IC719 1 2; IC811 1 2; IC812 1 2

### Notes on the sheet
- ※CN508 is connected to CN8 of RD210-SCHEMATIC1
- ※CN509 is connected to CN9 of RD210-SCHEMATIC1
- ※CN910 is connected to CN10 of RD210-SCHEMATIC1
- <Current Sensing Circuit>
- BLOCK 0:Hi-Voltage Side
- BLOCK 0:Low-Voltage Side
- BLOCK 0:Coil Current

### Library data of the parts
C710 C711 C720 C721 C910 C911 = C: VAL1: 0.1uF(K); VAL2: 50V; OriginalSymbolOrigin: (2540,7620)
C712-C718 C722-C728 C913-C919 = C: OriginalSymbolOrigin: (2540,7620)
C719 C729 = C: VAL1: 4.7nF(J); VAL2: 50V; OriginalSymbolOrigin: (2540,7620)
CN501 CN503 CN504 CN506 CN911 CN913 = C2A: as CN6 on sheet 8
CN502 CN505 CN912 = TP: as CN957 on sheet 6
CN508 CN509 CN910 = B2P-VH: MANUFACTURER: PHOENIX CONTACT; ITEM: Connector 2Pin Terminal Block; SCH_NAME: MCV1,5/2-G-3.5; TIME: 08:44:48; UPDATEUSER: sptcae13; UPDATETIME: 17:31:47; SAVECOUNT: 5; SAVEAREA0: -87042,-47887,89765,32676; OriginalSymbolOrigin: (0,0); CDBNAME: CN
D711-D713 = DEW: SAVEAREA0: -10024,-234,32508,20938; TIME: 14:49:55; UPDATEUSER: 19990028; UPDATETIME: 14:00:58; SAVECOUNT: 4; OriginalSymbolOrigin: (5080,17780); CDBNAME: D
IC710-IC712 IC719 IC811 IC812 = TLVH431AQDBVRQ1: MANUFACTURER: Panasonic; ITEM: Register; SIZECODESMD: 1608; VLUE4: (B); TIME: 08:44:47; UPDATEUSER: sptcae13; UPDATETIME: 17:49:34; SAVECOUNT: 11; SAVEAREA0: -8264,-23317,25334,1279; OriginalSymbolOrigin: (2540,0); CDBNAME: IC
IC713 IC714 IC716 IC717 IC813 IC814 = INA290A2QDCKRQ1: MANUFACTURER: TOSHIBA; ITEM: IC Logic; TIME: 08:44:45; UPDATEUSER: sptcae13; UPDATETIME: 08:56:52; SAVECOUNT: 17; SAVEAREA0: -4733,-13253,17562,3068; OriginalSymbolOrigin: (2540,0); CDBNAME: IC
IC715 IC718 IC815 IC816 = TS5A3159QDBVRQ1: MANUFACTURER: Panasonic; ITEM: Register; SIZECODESMD: 1608; VLUE4: (B); TIME: 08:44:47; UPDATEUSER: sptcae13; UPDATETIME: 19:09:10; SAVECOUNT: 15; SAVEAREA0: -8264,-23317,25334,1279; OriginalSymbolOrigin: (2540,0); CDBNAME: IC
Q711 Q713 Q716 Q718 Q815 Q817 = TRN: as Q801 on sheet 8
Q712 Q714 Q717 Q719 Q816 Q818 = RN4907_Q2: 7TH PART FIELD: RES.,; 4TH PART FIELD: VISHAY,; 3RD PART FIELD: CHIP; 2ND PART FIELD: 1-5%; 5TH PART FIELD: CRCW0805---RT6; 1ST PART FIELD: 1/8W; PARTS: 1; VAL1: VALUE; TIME: 08:44:45; UPDATEUSER: t4887876; UPDATETIME: 19:03:09; SAVECOUNT: 13; CLASS: DISCRETE; HETERO: RN4905_1,RN4905_2; FUNCTION: PNP&NPN_PCT; LEVEL: STD; PKG_TYPE: 2-2J1A; DEVICE: RN4905; SAVEAREA0: -13854,-30480,41847,0; DEVICENAME: DTC144EETL; OriginalSymbolOrigin: (0,12700); CaptureCellPackProp: RN4907_Q2A; COMPONENTNAME: RN4907_1
R701 R711 R716 R901 R911 R916 = R: OriginalSymbolOrigin: (5080,5080)
R706 R724-R727 R736-R738 R824-R827 R836-R838 R906 R924-R927 R936 R937 = R: VAL2: 125mW; OriginalSymbolOrigin: (5080,5080)
R720 R721 R820 R821 R920 R921 = R: VAL2: 100mW; VAL1: 1k(F); OriginalSymbolOrigin: (5080,5080)
R722 R723 R728 R729 R734 R735 R822 R823 R828 R829 R834 R835 R922 R923 R928 R929 R934 R935 = R: as R819 on sheet 8
R730-R733 R830-R833 R930-R933 = R: as R816 on sheet 8
R739 R839 R939 = R: VAL2: 100mW; VAL1: 10(F); OriginalSymbolOrigin: (5080,5080)
U?#9 = WAKU_DEF_A3: PLOTTIME: HH:MM; SAVEAREA0: 96913,-567914,509243,-368858; TIME: 14:30:25; UPDATEUSER: t5459927; UPDATETIME: 06:47:03; SAVECOUNT: 20; ZONEOFFSETX: 36; ZONEOFFSETY: -24; OriginalSymbolOrigin: (12700,-12700); SHTSAVECOUNT: 140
